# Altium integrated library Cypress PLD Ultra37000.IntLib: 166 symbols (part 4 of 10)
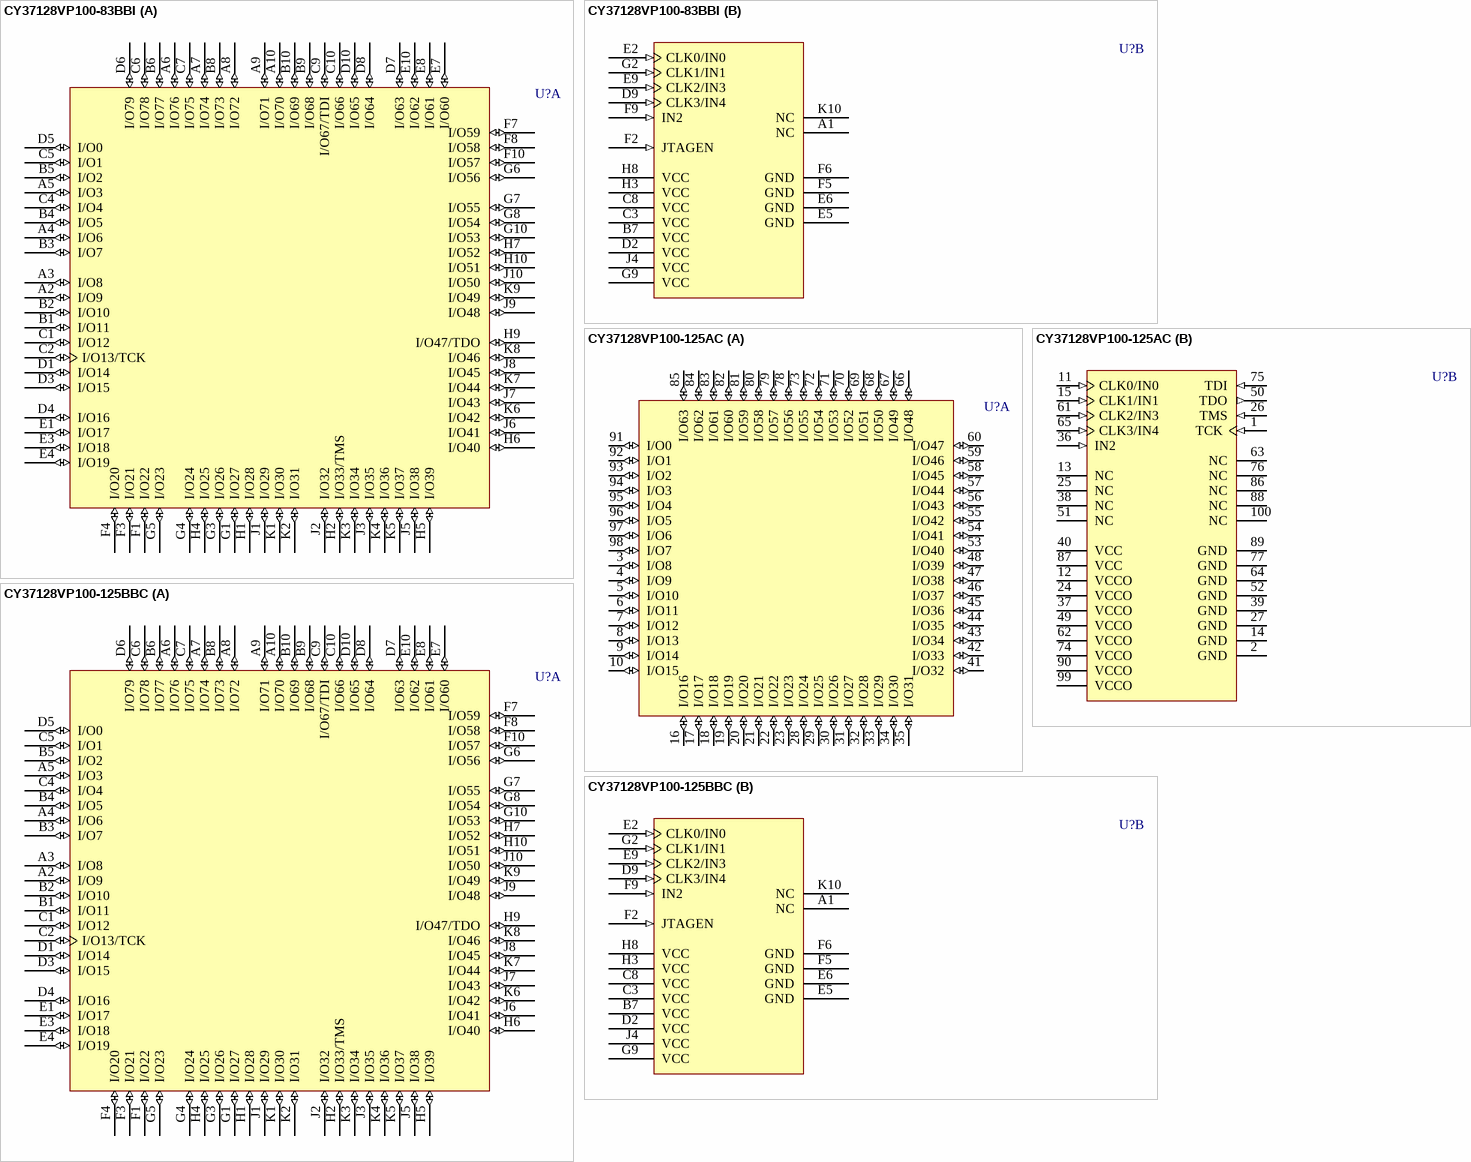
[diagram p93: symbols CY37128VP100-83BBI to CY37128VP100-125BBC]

## CY37128VP100-125AC
designator U?
Ultra37000 3.3V, ISR High-Performance CPLD
footprint A100_N (Thin QFP, 100-Leads, Body 14x14mm, Pitch 0.5mm, IPC Medium Density)
footprint A100_L (Thin QFP, 100-Leads, Body 14x14mm, Pitch 0.5mm, IPC High Density)
footprint A100_M (Thin QFP, 100-Leads, Body 14x14mm, Pitch 0.5mm, IPC Low Density)
3D model CY37128VP100-A100 (100-Pin Thin Quad Flat Pack 0.5 mm Pitch)
part A pins: 3 I/O8 (io), 4 I/O9 (io), 5 I/O10 (io), 6 I/O11 (io), 7 I/O12 (io), 8 I/O13 (io), 9 I/O14 (io), 10 I/O15 (io), 16 I/O16 (io), 17 I/O17 (io), 18 I/O18 (io), 19 I/O19 (io), 20 I/O20 (io), 21 I/O21 (io), 22 I/O22 (io), 23 I/O23 (io), 28 I/O24 (io), 29 I/O25 (io), 30 I/O26 (io), 31 I/O27 (io), 32 I/O28 (io), 33 I/O29 (io), 34 I/O30 (io), 35 I/O31 (io), 41 I/O32 (io), 42 I/O33 (io), 43 I/O34 (io), 44 I/O35 (io), 45 I/O36 (io), 46 I/O37 (io), 47 I/O38 (io), 48 I/O39 (io), 53 I/O40 (io), 54 I/O41 (io), 55 I/O42 (io), 56 I/O43 (io), 57 I/O44 (io), 58 I/O45 (io), 59 I/O46 (io), 60 I/O47 (io), 66 I/O48 (io), 67 I/O49 (io), 68 I/O50 (io), 69 I/O51 (io), 70 I/O52 (io), 71 I/O53 (io), 72 I/O54 (io), 73 I/O55 (io), 78 I/O56 (io), 79 I/O57 (io), 80 I/O58 (io), 81 I/O59 (io), 82 I/O60 (io), 83 I/O61 (io), 84 I/O62 (io), 85 I/O63 (io), 91 I/O0 (io), 92 I/O1 (io), 93 I/O2 (io), 94 I/O3 (io), 95 I/O4 (io), 96 I/O5 (io), 97 I/O6 (io), 98 I/O7 (io)
part B pins: 1 TCK (in), 2 GND (power), 11 CLK0/IN0 (in), 12 VCCO (power), 13 NC, 14 GND (power), 15 CLK1/IN1 (in), 24 VCCO (power), 25 NC, 26 TMS (in), 27 GND (power), 36 IN2 (in), 37 VCCO (power), 38 NC, 39 GND (power), 40 VCC (power), 49 VCCO (power), 50 TDO (out), 51 NC, 52 GND (power), 61 CLK2/IN3 (in), 62 VCCO (power), 63 NC, 64 GND (power), 65 CLK3/IN4 (in), 74 VCCO (power), 75 TDI (in), 76 NC, 77 GND (power), 86 NC, 87 VCC (power), 88 NC, 89 GND (power), 90 VCCO (power), 99 VCCO (power), 100 NC

## CY37128VP100-125BBC
designator U?
Ultra37000 3.3V, ISR High-Performance CPLD
footprint BB100 (BGA, 100-Leads, Body 11x11mm, Pitch 1mm)
3D model CY37128VP100-BB100 (100-Ball Thin Ball Grid Array 1 mm Pitch)
part A pins: A2 I/O9 (io), A3 I/O8 (io), A4 I/O6 (io), A5 I/O3 (io), A6 I/O76 (io), A7 I/O74 (io), A8 I/O72 (io), A9 I/O71 (io), A10 I/O70 (io), B1 I/O11 (io), B2 I/O10 (io), B3 I/O7 (io), B4 I/O5 (io), B5 I/O2 (io), B6 I/O77 (io), B8 I/O73 (io), B9 I/O68 (io), B10 I/O69 (io), C1 I/O12 (io), C2 I/O13/TCK (io), C4 I/O4 (io), C5 I/O1 (io), C6 I/O78 (io), C7 I/O75 (io), C9 I/O67/TDI (io), C10 I/O66 (io), D1 I/O14 (io), D3 I/O15 (io), D4 I/O16 (io), D5 I/O0 (io), D6 I/O79 (io), D7 I/O63 (io), D8 I/O64 (io), D10 I/O65 (io), E1 I/O17 (io), E3 I/O18 (io), E4 I/O19 (io), E7 I/O60 (io), E8 I/O61 (io), E10 I/O62 (io), F1 I/O22 (io), F3 I/O21 (io), F4 I/O20 (io), F7 I/O59 (io), F8 I/O58 (io), F10 I/O57 (io), G1 I/O27 (io), G3 I/O26 (io), G4 I/O24 (io), G5 I/O23 (io), G6 I/O56 (io), G7 I/O55 (io), G8 I/O54 (io), G10 I/O53 (io), H1 I/O28 (io), H2 I/O33/TMS (io), H4 I/O25 (io), H5 I/O39 (io), H6 I/O40 (io), H7 I/O52 (io), H9 I/O47/TDO (io), H10 I/O51 (io), J1 I/O29 (io), J2 I/O32 (io), J3 I/O35 (io), J5 I/O38 (io), J6 I/O41 (io), J7 I/O43 (io), J8 I/O45 (io), J9 I/O48 (io), J10 I/O50 (io), K1 I/O30 (io), K2 I/O31 (io), K3 I/O34 (io), K4 I/O36 (io), K5 I/O37 (io), K6 I/O42 (io), K7 I/O44 (io), K8 I/O46 (io), K9 I/O49 (io)
part B pins: A1 NC, B7 VCC (power), C3 VCC (power), C8 VCC (power), D2 VCC (power), D9 CLK3/IN4 (in), E2 CLK0/IN0 (in), E5 GND (power), E6 GND (power), E9 CLK2/IN3 (in), F2 JTAGEN (in), F5 GND (power), F6 GND (power), F9 IN2 (in), G2 CLK1/IN1 (in), G9 VCC (power), H3 VCC (power), H8 VCC (power), J4 VCC (power), K10 NC

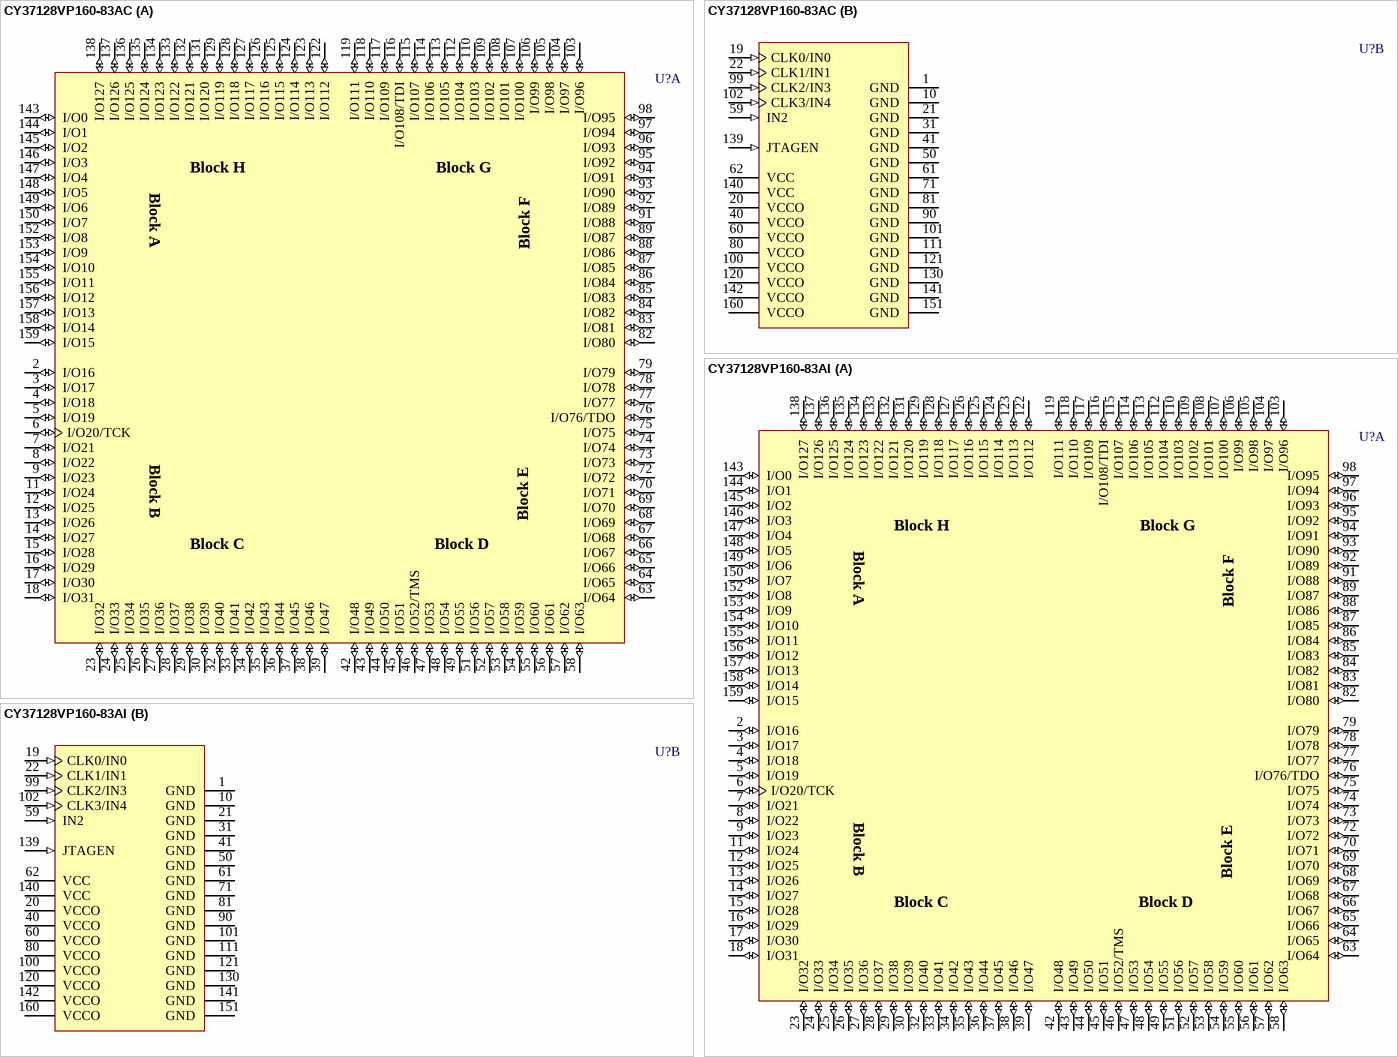
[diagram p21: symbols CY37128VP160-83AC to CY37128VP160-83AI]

## CY37128VP160-83AC
designator U?
Ultra37000 3.3V, ISR High-Performance CPLD
footprint A160_N (Thin QFP, 160-Leads, Body 24x24mm, Pitch 0.5mm, IPC Medium Density)
footprint A160_L (Thin QFP, 160-Leads, Body 24x24mm, Pitch 0.5mm, IPC High Density)
footprint A160_M (Thin QFP, 160-Leads, Body 24x24mm, Pitch 0.5mm, IPC Low Density)
3D model CY37128VP160-A160 (160-Pin Thin Quad Flat Pack 0.5 mm Pitch)
part A pins: 2 I/O16 (io), 3 I/O17 (io), 4 I/O18 (io), 5 I/O19 (io), 6 I/O20/TCK (io), 7 I/O21 (io), 8 I/O22 (io), 9 I/O23 (io), 11 I/O24 (io), 12 I/O25 (io), 13 I/O26 (io), 14 I/O27 (io), 15 I/O28 (io), 16 I/O29 (io), 17 I/O30 (io), 18 I/O31 (io), 23 I/O32 (io), 24 I/O33 (io), 25 I/O34 (io), 26 I/O35 (io), 27 I/O36 (io), 28 I/O37 (io), 29 I/O38 (io), 30 I/O39 (io), 32 I/O40 (io), 33 I/O41 (io), 34 I/O42 (io), 35 I/O43 (io), 36 I/O44 (io), 37 I/O45 (io), 38 I/O46 (io), 39 I/O47 (io), 42 I/O48 (io), 43 I/O49 (io), 44 I/O50 (io), 45 I/O51 (io), 46 I/O52/TMS (io), 47 I/O53 (io), 48 I/O54 (io), 49 I/O55 (io), 51 I/O56 (io), 52 I/O57 (io), 53 I/O58 (io), 54 I/O59 (io), 55 I/O60 (io), 56 I/O61 (io), 57 I/O62 (io), 58 I/O63 (io), 63 I/O64 (io), 64 I/O65 (io), 65 I/O66 (io), 66 I/O67 (io), 67 I/O68 (io), 68 I/O69 (io), 69 I/O70 (io), 70 I/O71 (io), 72 I/O72 (io), 73 I/O73 (io), 74 I/O74 (io), 75 I/O75 (io), 76 I/O76/TDO (io), 77 I/O77 (io), 78 I/O78 (io), 79 I/O79 (io), 82 I/O80 (io), 83 I/O81 (io), 84 I/O82 (io), 85 I/O83 (io), 86 I/O84 (io), 87 I/O85 (io), 88 I/O86 (io), 89 I/O87 (io), 91 I/O88 (io), 92 I/O89 (io), 93 I/O90 (io), 94 I/O91 (io), 95 I/O92 (io), 96 I/O93 (io), 97 I/O94 (io), 98 I/O95 (io), 103 I/O96 (io), 104 I/O97 (io), 105 I/O98 (io), 106 I/O99 (io), 107 I/O100 (io), 108 I/O101 (io), 109 I/O102 (io), 110 I/O103 (io), 112 I/O104 (io), 113 I/O105 (io), 114 I/O106 (io), 115 I/O107 (io), 116 I/O108/TDI (io), 117 I/O109 (io), 118 I/O110 (io), 119 I/O111 (io), 122 I/O112 (io), 123 I/O113 (io), 124 I/O114 (io), 125 I/O115 (io), 126 I/O116 (io), 127 I/O117 (io), 128 I/O118 (io), 129 I/O119 (io), 131 I/O120 (io), 132 I/O121 (io), 133 I/O122 (io), 134 I/O123 (io), 135 I/O124 (io), 136 I/O125 (io), 137 I/O126 (io), 138 I/O127 (io), 143 I/O0 (io), 144 I/O1 (io), 145 I/O2 (io), 146 I/O3 (io), 147 I/O4 (io), 148 I/O5 (io), 149 I/O6 (io), 150 I/O7 (io), 152 I/O8 (io), 153 I/O9 (io), 154 I/O10 (io), 155 I/O11 (io), 156 I/O12 (io), 157 I/O13 (io), 158 I/O14 (io), 159 I/O15 (io)
part B pins: 1 GND (power), 10 GND (power), 19 CLK0/IN0 (in), 20 VCCO (power), 21 GND (power), 22 CLK1/IN1 (in), 31 GND (power), 40 VCCO (power), 41 GND (power), 50 GND (power), 59 IN2 (in), 60 VCCO (power), 61 GND (power), 62 VCC (power), 71 GND (power), 80 VCCO (power), 81 GND (power), 90 GND (power), 99 CLK2/IN3 (in), 100 VCCO (power), 101 GND (power), 102 CLK3/IN4 (in), 111 GND (power), 120 VCCO (power), 121 GND (power), 130 GND (power), 139 JTAGEN (in), 140 VCC (power), 141 GND (power), 142 VCCO (power), 151 GND (power), 160 VCCO (power)

## CY37128VP160-83AI
designator U?
Ultra37000 3.3V, ISR High-Performance CPLD
footprint A160_N (Thin QFP, 160-Leads, Body 24x24mm, Pitch 0.5mm, IPC Medium Density)
footprint A160_L (Thin QFP, 160-Leads, Body 24x24mm, Pitch 0.5mm, IPC High Density)
footprint A160_M (Thin QFP, 160-Leads, Body 24x24mm, Pitch 0.5mm, IPC Low Density)
3D model CY37128VP160-A160 (160-Pin Thin Quad Flat Pack 0.5 mm Pitch)
part A pins: 2 I/O16 (io), 3 I/O17 (io), 4 I/O18 (io), 5 I/O19 (io), 6 I/O20/TCK (io), 7 I/O21 (io), 8 I/O22 (io), 9 I/O23 (io), 11 I/O24 (io), 12 I/O25 (io), 13 I/O26 (io), 14 I/O27 (io), 15 I/O28 (io), 16 I/O29 (io), 17 I/O30 (io), 18 I/O31 (io), 23 I/O32 (io), 24 I/O33 (io), 25 I/O34 (io), 26 I/O35 (io), 27 I/O36 (io), 28 I/O37 (io), 29 I/O38 (io), 30 I/O39 (io), 32 I/O40 (io), 33 I/O41 (io), 34 I/O42 (io), 35 I/O43 (io), 36 I/O44 (io), 37 I/O45 (io), 38 I/O46 (io), 39 I/O47 (io), 42 I/O48 (io), 43 I/O49 (io), 44 I/O50 (io), 45 I/O51 (io), 46 I/O52/TMS (io), 47 I/O53 (io), 48 I/O54 (io), 49 I/O55 (io), 51 I/O56 (io), 52 I/O57 (io), 53 I/O58 (io), 54 I/O59 (io), 55 I/O60 (io), 56 I/O61 (io), 57 I/O62 (io), 58 I/O63 (io), 63 I/O64 (io), 64 I/O65 (io), 65 I/O66 (io), 66 I/O67 (io), 67 I/O68 (io), 68 I/O69 (io), 69 I/O70 (io), 70 I/O71 (io), 72 I/O72 (io), 73 I/O73 (io), 74 I/O74 (io), 75 I/O75 (io), 76 I/O76/TDO (io), 77 I/O77 (io), 78 I/O78 (io), 79 I/O79 (io), 82 I/O80 (io), 83 I/O81 (io), 84 I/O82 (io), 85 I/O83 (io), 86 I/O84 (io), 87 I/O85 (io), 88 I/O86 (io), 89 I/O87 (io), 91 I/O88 (io), 92 I/O89 (io), 93 I/O90 (io), 94 I/O91 (io), 95 I/O92 (io), 96 I/O93 (io), 97 I/O94 (io), 98 I/O95 (io), 103 I/O96 (io), 104 I/O97 (io), 105 I/O98 (io), 106 I/O99 (io), 107 I/O100 (io), 108 I/O101 (io), 109 I/O102 (io), 110 I/O103 (io), 112 I/O104 (io), 113 I/O105 (io), 114 I/O106 (io), 115 I/O107 (io), 116 I/O108/TDI (io), 117 I/O109 (io), 118 I/O110 (io), 119 I/O111 (io), 122 I/O112 (io), 123 I/O113 (io), 124 I/O114 (io), 125 I/O115 (io), 126 I/O116 (io), 127 I/O117 (io), 128 I/O118 (io), 129 I/O119 (io), 131 I/O120 (io), 132 I/O121 (io), 133 I/O122 (io), 134 I/O123 (io), 135 I/O124 (io), 136 I/O125 (io), 137 I/O126 (io), 138 I/O127 (io), 143 I/O0 (io), 144 I/O1 (io), 145 I/O2 (io), 146 I/O3 (io), 147 I/O4 (io), 148 I/O5 (io), 149 I/O6 (io), 150 I/O7 (io), 152 I/O8 (io), 153 I/O9 (io), 154 I/O10 (io), 155 I/O11 (io), 156 I/O12 (io), 157 I/O13 (io), 158 I/O14 (io), 159 I/O15 (io)
part B pins: 1 GND (power), 10 GND (power), 19 CLK0/IN0 (in), 20 VCCO (power), 21 GND (power), 22 CLK1/IN1 (in), 31 GND (power), 40 VCCO (power), 41 GND (power), 50 GND (power), 59 IN2 (in), 60 VCCO (power), 61 GND (power), 62 VCC (power), 71 GND (power), 80 VCCO (power), 81 GND (power), 90 GND (power), 99 CLK2/IN3 (in), 100 VCCO (power), 101 GND (power), 102 CLK3/IN4 (in), 111 GND (power), 120 VCCO (power), 121 GND (power), 130 GND (power), 139 JTAGEN (in), 140 VCC (power), 141 GND (power), 142 VCCO (power), 151 GND (power), 160 VCCO (power)

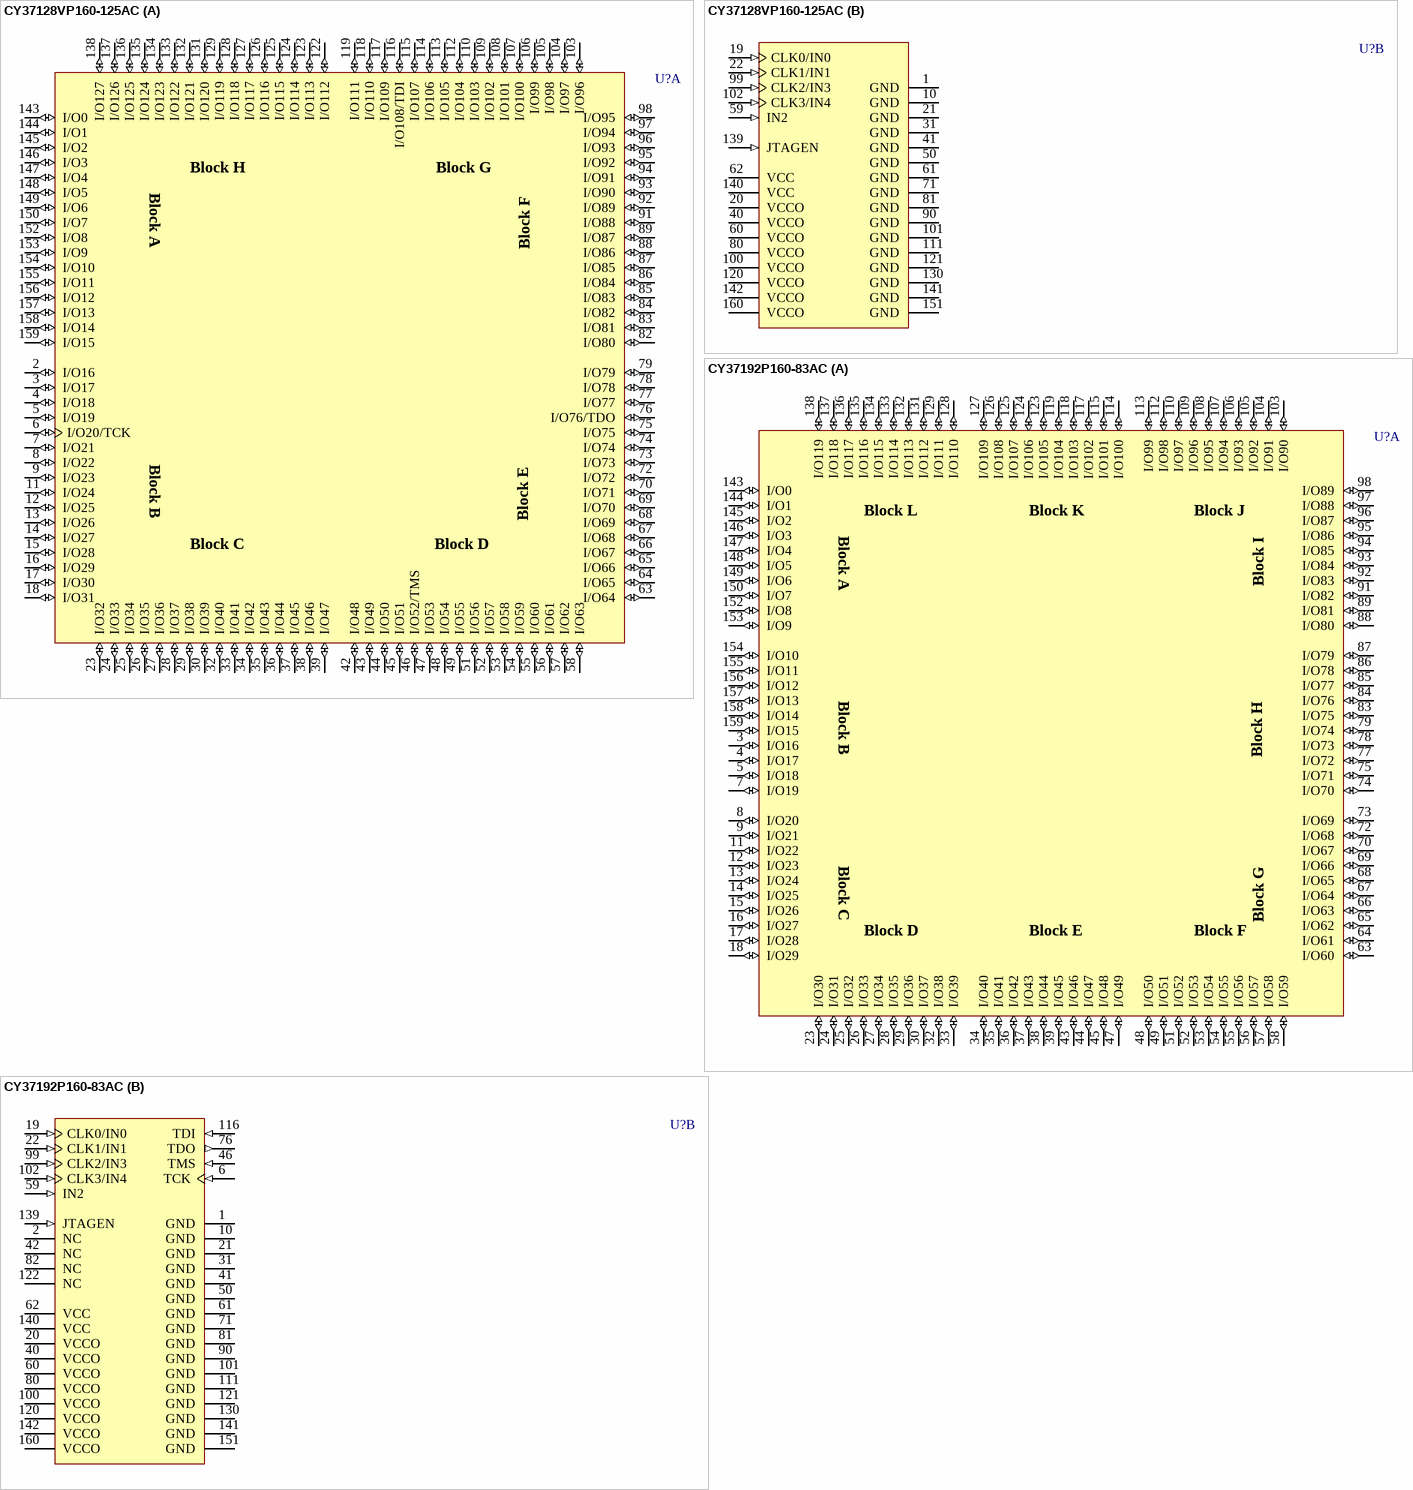
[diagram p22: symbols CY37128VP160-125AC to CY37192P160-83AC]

## CY37128VP160-125AC
designator U?
Ultra37000 3.3V, ISR High-Performance CPLD
footprint A160_N (Thin QFP, 160-Leads, Body 24x24mm, Pitch 0.5mm, IPC Medium Density)
footprint A160_L (Thin QFP, 160-Leads, Body 24x24mm, Pitch 0.5mm, IPC High Density)
footprint A160_M (Thin QFP, 160-Leads, Body 24x24mm, Pitch 0.5mm, IPC Low Density)
3D model CY37128VP160-A160 (160-Pin Thin Quad Flat Pack 0.5 mm Pitch)
part A pins: 2 I/O16 (io), 3 I/O17 (io), 4 I/O18 (io), 5 I/O19 (io), 6 I/O20/TCK (io), 7 I/O21 (io), 8 I/O22 (io), 9 I/O23 (io), 11 I/O24 (io), 12 I/O25 (io), 13 I/O26 (io), 14 I/O27 (io), 15 I/O28 (io), 16 I/O29 (io), 17 I/O30 (io), 18 I/O31 (io), 23 I/O32 (io), 24 I/O33 (io), 25 I/O34 (io), 26 I/O35 (io), 27 I/O36 (io), 28 I/O37 (io), 29 I/O38 (io), 30 I/O39 (io), 32 I/O40 (io), 33 I/O41 (io), 34 I/O42 (io), 35 I/O43 (io), 36 I/O44 (io), 37 I/O45 (io), 38 I/O46 (io), 39 I/O47 (io), 42 I/O48 (io), 43 I/O49 (io), 44 I/O50 (io), 45 I/O51 (io), 46 I/O52/TMS (io), 47 I/O53 (io), 48 I/O54 (io), 49 I/O55 (io), 51 I/O56 (io), 52 I/O57 (io), 53 I/O58 (io), 54 I/O59 (io), 55 I/O60 (io), 56 I/O61 (io), 57 I/O62 (io), 58 I/O63 (io), 63 I/O64 (io), 64 I/O65 (io), 65 I/O66 (io), 66 I/O67 (io), 67 I/O68 (io), 68 I/O69 (io), 69 I/O70 (io), 70 I/O71 (io), 72 I/O72 (io), 73 I/O73 (io), 74 I/O74 (io), 75 I/O75 (io), 76 I/O76/TDO (io), 77 I/O77 (io), 78 I/O78 (io), 79 I/O79 (io), 82 I/O80 (io), 83 I/O81 (io), 84 I/O82 (io), 85 I/O83 (io), 86 I/O84 (io), 87 I/O85 (io), 88 I/O86 (io), 89 I/O87 (io), 91 I/O88 (io), 92 I/O89 (io), 93 I/O90 (io), 94 I/O91 (io), 95 I/O92 (io), 96 I/O93 (io), 97 I/O94 (io), 98 I/O95 (io), 103 I/O96 (io), 104 I/O97 (io), 105 I/O98 (io), 106 I/O99 (io), 107 I/O100 (io), 108 I/O101 (io), 109 I/O102 (io), 110 I/O103 (io), 112 I/O104 (io), 113 I/O105 (io), 114 I/O106 (io), 115 I/O107 (io), 116 I/O108/TDI (io), 117 I/O109 (io), 118 I/O110 (io), 119 I/O111 (io), 122 I/O112 (io), 123 I/O113 (io), 124 I/O114 (io), 125 I/O115 (io), 126 I/O116 (io), 127 I/O117 (io), 128 I/O118 (io), 129 I/O119 (io), 131 I/O120 (io), 132 I/O121 (io), 133 I/O122 (io), 134 I/O123 (io), 135 I/O124 (io), 136 I/O125 (io), 137 I/O126 (io), 138 I/O127 (io), 143 I/O0 (io), 144 I/O1 (io), 145 I/O2 (io), 146 I/O3 (io), 147 I/O4 (io), 148 I/O5 (io), 149 I/O6 (io), 150 I/O7 (io), 152 I/O8 (io), 153 I/O9 (io), 154 I/O10 (io), 155 I/O11 (io), 156 I/O12 (io), 157 I/O13 (io), 158 I/O14 (io), 159 I/O15 (io)
part B pins: 1 GND (power), 10 GND (power), 19 CLK0/IN0 (in), 20 VCCO (power), 21 GND (power), 22 CLK1/IN1 (in), 31 GND (power), 40 VCCO (power), 41 GND (power), 50 GND (power), 59 IN2 (in), 60 VCCO (power), 61 GND (power), 62 VCC (power), 71 GND (power), 80 VCCO (power), 81 GND (power), 90 GND (power), 99 CLK2/IN3 (in), 100 VCCO (power), 101 GND (power), 102 CLK3/IN4 (in), 111 GND (power), 120 VCCO (power), 121 GND (power), 130 GND (power), 139 JTAGEN (in), 140 VCC (power), 141 GND (power), 142 VCCO (power), 151 GND (power), 160 VCCO (power)

## CY37192P160-83AC
designator U?
Ultra37000 5V, ISR High-Performance CPLD
footprint A160_N (Thin QFP, 160-Leads, Body 24x24mm, Pitch 0.5mm, IPC Medium Density)
footprint A160_L (Thin QFP, 160-Leads, Body 24x24mm, Pitch 0.5mm, IPC High Density)
footprint A160_M (Thin QFP, 160-Leads, Body 24x24mm, Pitch 0.5mm, IPC Low Density)
3D model CY37192P160-A160 (160-Pin Thin Quad Flat Pack 0.5 mm Pitch)
part A pins: 3 I/O16 (io), 4 I/O17 (io), 5 I/O18 (io), 7 I/O19 (io), 8 I/O20 (io), 9 I/O21 (io), 11 I/O22 (io), 12 I/O23 (io), 13 I/O24 (io), 14 I/O25 (io), 15 I/O26 (io), 16 I/O27 (io), 17 I/O28 (io), 18 I/O29 (io), 23 I/O30 (io), 24 I/O31 (io), 25 I/O32 (io), 26 I/O33 (io), 27 I/O34 (io), 28 I/O35 (io), 29 I/O36 (io), 30 I/O37 (io), 32 I/O38 (io), 33 I/O39 (io), 34 I/O40 (io), 35 I/O41 (io), 36 I/O42 (io), 37 I/O43 (io), 38 I/O44 (io), 39 I/O45 (io), 43 I/O46 (io), 44 I/O47 (io), 45 I/O48 (io), 47 I/O49 (io), 48 I/O50 (io), 49 I/O51 (io), 51 I/O52 (io), 52 I/O53 (io), 53 I/O54 (io), 54 I/O55 (io), 55 I/O56 (io), 56 I/O57 (io), 57 I/O58 (io), 58 I/O59 (io), 63 I/O60 (io), 64 I/O61 (io), 65 I/O62 (io), 66 I/O63 (io), 67 I/O64 (io), 68 I/O65 (io), 69 I/O66 (io), 70 I/O67 (io), 72 I/O68 (io), 73 I/O69 (io), 74 I/O70 (io), 75 I/O71 (io), 77 I/O72 (io), 78 I/O73 (io), 79 I/O74 (io), 83 I/O75 (io), 84 I/O76 (io), 85 I/O77 (io), 86 I/O78 (io), 87 I/O79 (io), 88 I/O80 (io), 89 I/O81 (io), 91 I/O82 (io), 92 I/O83 (io), 93 I/O84 (io), 94 I/O85 (io), 95 I/O86 (io), 96 I/O87 (io), 97 I/O88 (io), 98 I/O89 (io), 103 I/O90 (io), 104 I/O91 (io), 105 I/O92 (io), 106 I/O93 (io), 107 I/O94 (io), 108 I/O95 (io), 109 I/O96 (io), 110 I/O97 (io), 112 I/O98 (io), 113 I/O99 (io), 114 I/O100 (io), 115 I/O101 (io), 117 I/O102 (io), 118 I/O103 (io), 119 I/O104 (io), 123 I/O105 (io), 124 I/O106 (io), 125 I/O107 (io), 126 I/O108 (io), 127 I/O109 (io), 128 I/O110 (io), 129 I/O111 (io), 131 I/O112 (io), 132 I/O113 (io), 133 I/O114 (io), 134 I/O115 (io), 135 I/O116 (io), 136 I/O117 (io), 137 I/O118 (io), 138 I/O119 (io), 143 I/O0 (io), 144 I/O1 (io), 145 I/O2 (io), 146 I/O3 (io), 147 I/O4 (io), 148 I/O5 (io), 149 I/O6 (io), 150 I/O7 (io), 152 I/O8 (io), 153 I/O9 (io), 154 I/O10 (io), 155 I/O11 (io), 156 I/O12 (io), 157 I/O13 (io), 158 I/O14 (io), 159 I/O15 (io)
part B pins: 1 GND (power), 2 NC, 6 TCK (in), 10 GND (power), 19 CLK0/IN0 (in), 20 VCCO (power), 21 GND (power), 22 CLK1/IN1 (in), 31 GND (power), 40 VCCO (power), 41 GND (power), 42 NC, 46 TMS (in), 50 GND (power), 59 IN2 (in), 60 VCCO (power), 61 GND (power), 62 VCC (power), 71 GND (power), 76 TDO (out), 80 VCCO (power), 81 GND (power), 82 NC, 90 GND (power), 99 CLK2/IN3 (in), 100 VCCO (power), 101 GND (power), 102 CLK3/IN4 (in), 111 GND (power), 116 TDI (in), 120 VCCO (power), 121 GND (power), 122 NC, 130 GND (power), 139 JTAGEN (in), 140 VCC (power), 141 GND (power), 142 VCCO (power), 151 GND (power), 160 VCCO (power)

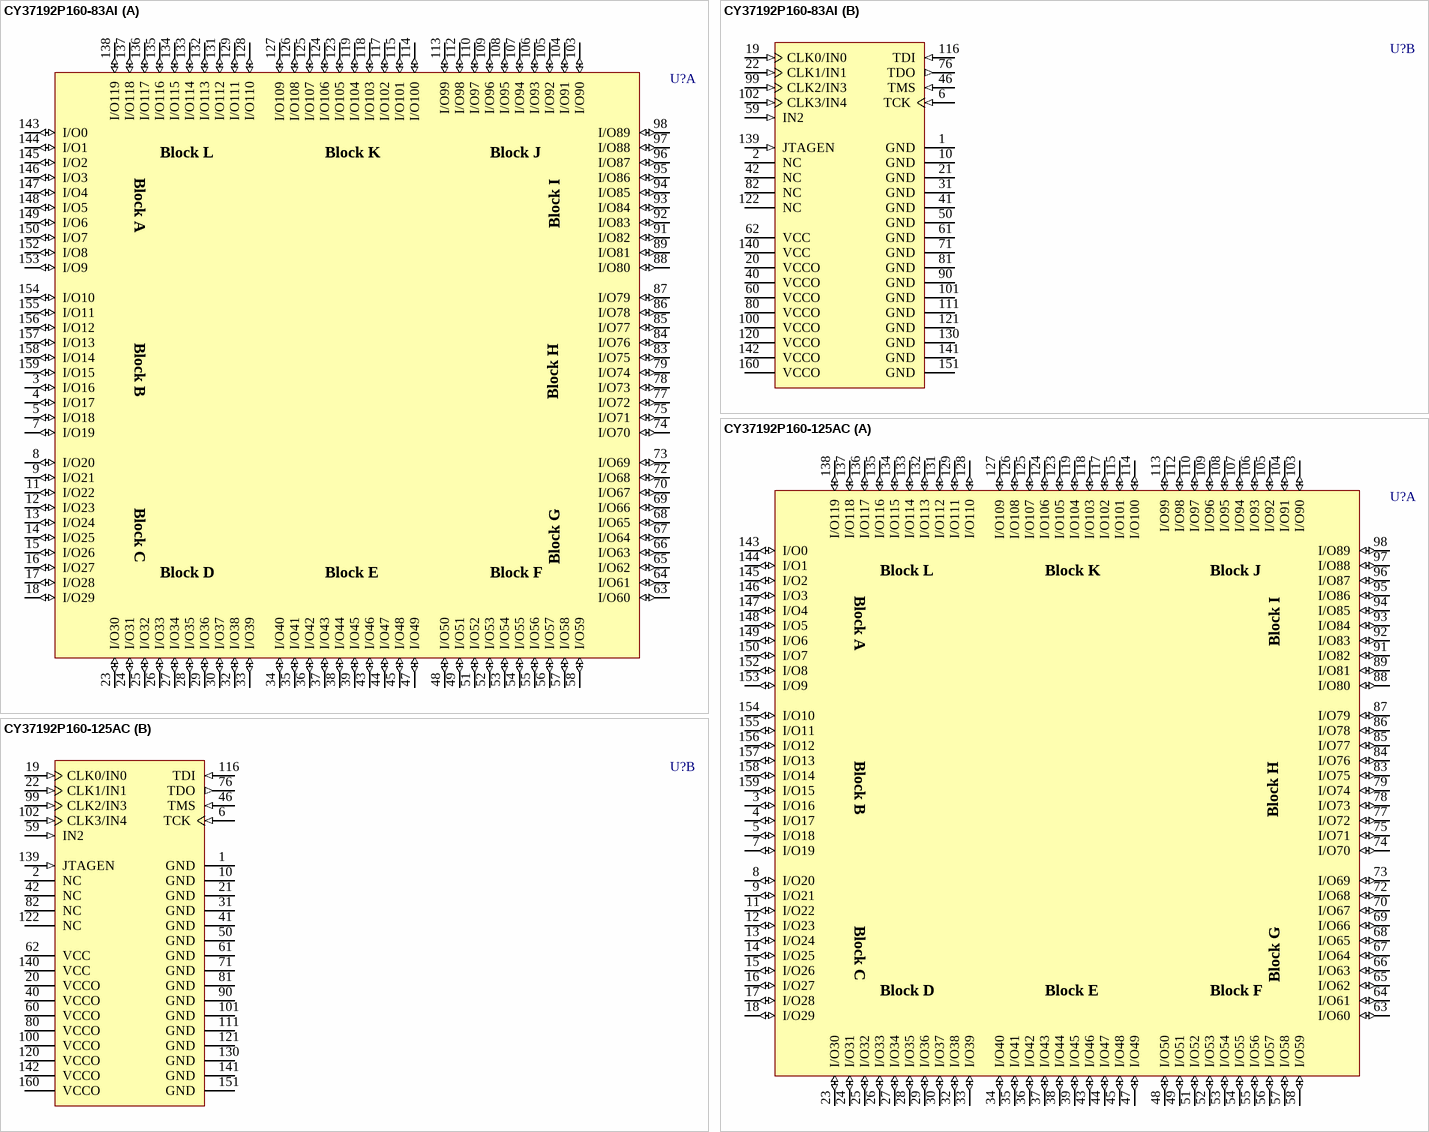
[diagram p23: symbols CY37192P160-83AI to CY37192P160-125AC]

## CY37192P160-83AI
designator U?
Ultra37000 5V, ISR High-Performance CPLD
footprint A160_N (Thin QFP, 160-Leads, Body 24x24mm, Pitch 0.5mm, IPC Medium Density)
footprint A160_L (Thin QFP, 160-Leads, Body 24x24mm, Pitch 0.5mm, IPC High Density)
footprint A160_M (Thin QFP, 160-Leads, Body 24x24mm, Pitch 0.5mm, IPC Low Density)
3D model CY37192P160-A160 (160-Pin Thin Quad Flat Pack 0.5 mm Pitch)
part A pins: 3 I/O16 (io), 4 I/O17 (io), 5 I/O18 (io), 7 I/O19 (io), 8 I/O20 (io), 9 I/O21 (io), 11 I/O22 (io), 12 I/O23 (io), 13 I/O24 (io), 14 I/O25 (io), 15 I/O26 (io), 16 I/O27 (io), 17 I/O28 (io), 18 I/O29 (io), 23 I/O30 (io), 24 I/O31 (io), 25 I/O32 (io), 26 I/O33 (io), 27 I/O34 (io), 28 I/O35 (io), 29 I/O36 (io), 30 I/O37 (io), 32 I/O38 (io), 33 I/O39 (io), 34 I/O40 (io), 35 I/O41 (io), 36 I/O42 (io), 37 I/O43 (io), 38 I/O44 (io), 39 I/O45 (io), 43 I/O46 (io), 44 I/O47 (io), 45 I/O48 (io), 47 I/O49 (io), 48 I/O50 (io), 49 I/O51 (io), 51 I/O52 (io), 52 I/O53 (io), 53 I/O54 (io), 54 I/O55 (io), 55 I/O56 (io), 56 I/O57 (io), 57 I/O58 (io), 58 I/O59 (io), 63 I/O60 (io), 64 I/O61 (io), 65 I/O62 (io), 66 I/O63 (io), 67 I/O64 (io), 68 I/O65 (io), 69 I/O66 (io), 70 I/O67 (io), 72 I/O68 (io), 73 I/O69 (io), 74 I/O70 (io), 75 I/O71 (io), 77 I/O72 (io), 78 I/O73 (io), 79 I/O74 (io), 83 I/O75 (io), 84 I/O76 (io), 85 I/O77 (io), 86 I/O78 (io), 87 I/O79 (io), 88 I/O80 (io), 89 I/O81 (io), 91 I/O82 (io), 92 I/O83 (io), 93 I/O84 (io), 94 I/O85 (io), 95 I/O86 (io), 96 I/O87 (io), 97 I/O88 (io), 98 I/O89 (io), 103 I/O90 (io), 104 I/O91 (io), 105 I/O92 (io), 106 I/O93 (io), 107 I/O94 (io), 108 I/O95 (io), 109 I/O96 (io), 110 I/O97 (io), 112 I/O98 (io), 113 I/O99 (io), 114 I/O100 (io), 115 I/O101 (io), 117 I/O102 (io), 118 I/O103 (io), 119 I/O104 (io), 123 I/O105 (io), 124 I/O106 (io), 125 I/O107 (io), 126 I/O108 (io), 127 I/O109 (io), 128 I/O110 (io), 129 I/O111 (io), 131 I/O112 (io), 132 I/O113 (io), 133 I/O114 (io), 134 I/O115 (io), 135 I/O116 (io), 136 I/O117 (io), 137 I/O118 (io), 138 I/O119 (io), 143 I/O0 (io), 144 I/O1 (io), 145 I/O2 (io), 146 I/O3 (io), 147 I/O4 (io), 148 I/O5 (io), 149 I/O6 (io), 150 I/O7 (io), 152 I/O8 (io), 153 I/O9 (io), 154 I/O10 (io), 155 I/O11 (io), 156 I/O12 (io), 157 I/O13 (io), 158 I/O14 (io), 159 I/O15 (io)
part B pins: 1 GND (power), 2 NC, 6 TCK (in), 10 GND (power), 19 CLK0/IN0 (in), 20 VCCO (power), 21 GND (power), 22 CLK1/IN1 (in), 31 GND (power), 40 VCCO (power), 41 GND (power), 42 NC, 46 TMS (in), 50 GND (power), 59 IN2 (in), 60 VCCO (power), 61 GND (power), 62 VCC (power), 71 GND (power), 76 TDO (out), 80 VCCO (power), 81 GND (power), 82 NC, 90 GND (power), 99 CLK2/IN3 (in), 100 VCCO (power), 101 GND (power), 102 CLK3/IN4 (in), 111 GND (power), 116 TDI (in), 120 VCCO (power), 121 GND (power), 122 NC, 130 GND (power), 139 JTAGEN (in), 140 VCC (power), 141 GND (power), 142 VCCO (power), 151 GND (power), 160 VCCO (power)

## CY37192P160-125AC
designator U?
Ultra37000 5V, ISR High-Performance CPLD
footprint A160_N (Thin QFP, 160-Leads, Body 24x24mm, Pitch 0.5mm, IPC Medium Density)
footprint A160_L (Thin QFP, 160-Leads, Body 24x24mm, Pitch 0.5mm, IPC High Density)
footprint A160_M (Thin QFP, 160-Leads, Body 24x24mm, Pitch 0.5mm, IPC Low Density)
3D model CY37192P160-A160 (160-Pin Thin Quad Flat Pack 0.5 mm Pitch)
part A pins: 3 I/O16 (io), 4 I/O17 (io), 5 I/O18 (io), 7 I/O19 (io), 8 I/O20 (io), 9 I/O21 (io), 11 I/O22 (io), 12 I/O23 (io), 13 I/O24 (io), 14 I/O25 (io), 15 I/O26 (io), 16 I/O27 (io), 17 I/O28 (io), 18 I/O29 (io), 23 I/O30 (io), 24 I/O31 (io), 25 I/O32 (io), 26 I/O33 (io), 27 I/O34 (io), 28 I/O35 (io), 29 I/O36 (io), 30 I/O37 (io), 32 I/O38 (io), 33 I/O39 (io), 34 I/O40 (io), 35 I/O41 (io), 36 I/O42 (io), 37 I/O43 (io), 38 I/O44 (io), 39 I/O45 (io), 43 I/O46 (io), 44 I/O47 (io), 45 I/O48 (io), 47 I/O49 (io), 48 I/O50 (io), 49 I/O51 (io), 51 I/O52 (io), 52 I/O53 (io), 53 I/O54 (io), 54 I/O55 (io), 55 I/O56 (io), 56 I/O57 (io), 57 I/O58 (io), 58 I/O59 (io), 63 I/O60 (io), 64 I/O61 (io), 65 I/O62 (io), 66 I/O63 (io), 67 I/O64 (io), 68 I/O65 (io), 69 I/O66 (io), 70 I/O67 (io), 72 I/O68 (io), 73 I/O69 (io), 74 I/O70 (io), 75 I/O71 (io), 77 I/O72 (io), 78 I/O73 (io), 79 I/O74 (io), 83 I/O75 (io), 84 I/O76 (io), 85 I/O77 (io), 86 I/O78 (io), 87 I/O79 (io), 88 I/O80 (io), 89 I/O81 (io), 91 I/O82 (io), 92 I/O83 (io), 93 I/O84 (io), 94 I/O85 (io), 95 I/O86 (io), 96 I/O87 (io), 97 I/O88 (io), 98 I/O89 (io), 103 I/O90 (io), 104 I/O91 (io), 105 I/O92 (io), 106 I/O93 (io), 107 I/O94 (io), 108 I/O95 (io), 109 I/O96 (io), 110 I/O97 (io), 112 I/O98 (io), 113 I/O99 (io), 114 I/O100 (io), 115 I/O101 (io), 117 I/O102 (io), 118 I/O103 (io), 119 I/O104 (io), 123 I/O105 (io), 124 I/O106 (io), 125 I/O107 (io), 126 I/O108 (io), 127 I/O109 (io), 128 I/O110 (io), 129 I/O111 (io), 131 I/O112 (io), 132 I/O113 (io), 133 I/O114 (io), 134 I/O115 (io), 135 I/O116 (io), 136 I/O117 (io), 137 I/O118 (io), 138 I/O119 (io), 143 I/O0 (io), 144 I/O1 (io), 145 I/O2 (io), 146 I/O3 (io), 147 I/O4 (io), 148 I/O5 (io), 149 I/O6 (io), 150 I/O7 (io), 152 I/O8 (io), 153 I/O9 (io), 154 I/O10 (io), 155 I/O11 (io), 156 I/O12 (io), 157 I/O13 (io), 158 I/O14 (io), 159 I/O15 (io)
part B pins: 1 GND (power), 2 NC, 6 TCK (in), 10 GND (power), 19 CLK0/IN0 (in), 20 VCCO (power), 21 GND (power), 22 CLK1/IN1 (in), 31 GND (power), 40 VCCO (power), 41 GND (power), 42 NC, 46 TMS (in), 50 GND (power), 59 IN2 (in), 60 VCCO (power), 61 GND (power), 62 VCC (power), 71 GND (power), 76 TDO (out), 80 VCCO (power), 81 GND (power), 82 NC, 90 GND (power), 99 CLK2/IN3 (in), 100 VCCO (power), 101 GND (power), 102 CLK3/IN4 (in), 111 GND (power), 116 TDI (in), 120 VCCO (power), 121 GND (power), 122 NC, 130 GND (power), 139 JTAGEN (in), 140 VCC (power), 141 GND (power), 142 VCCO (power), 151 GND (power), 160 VCCO (power)

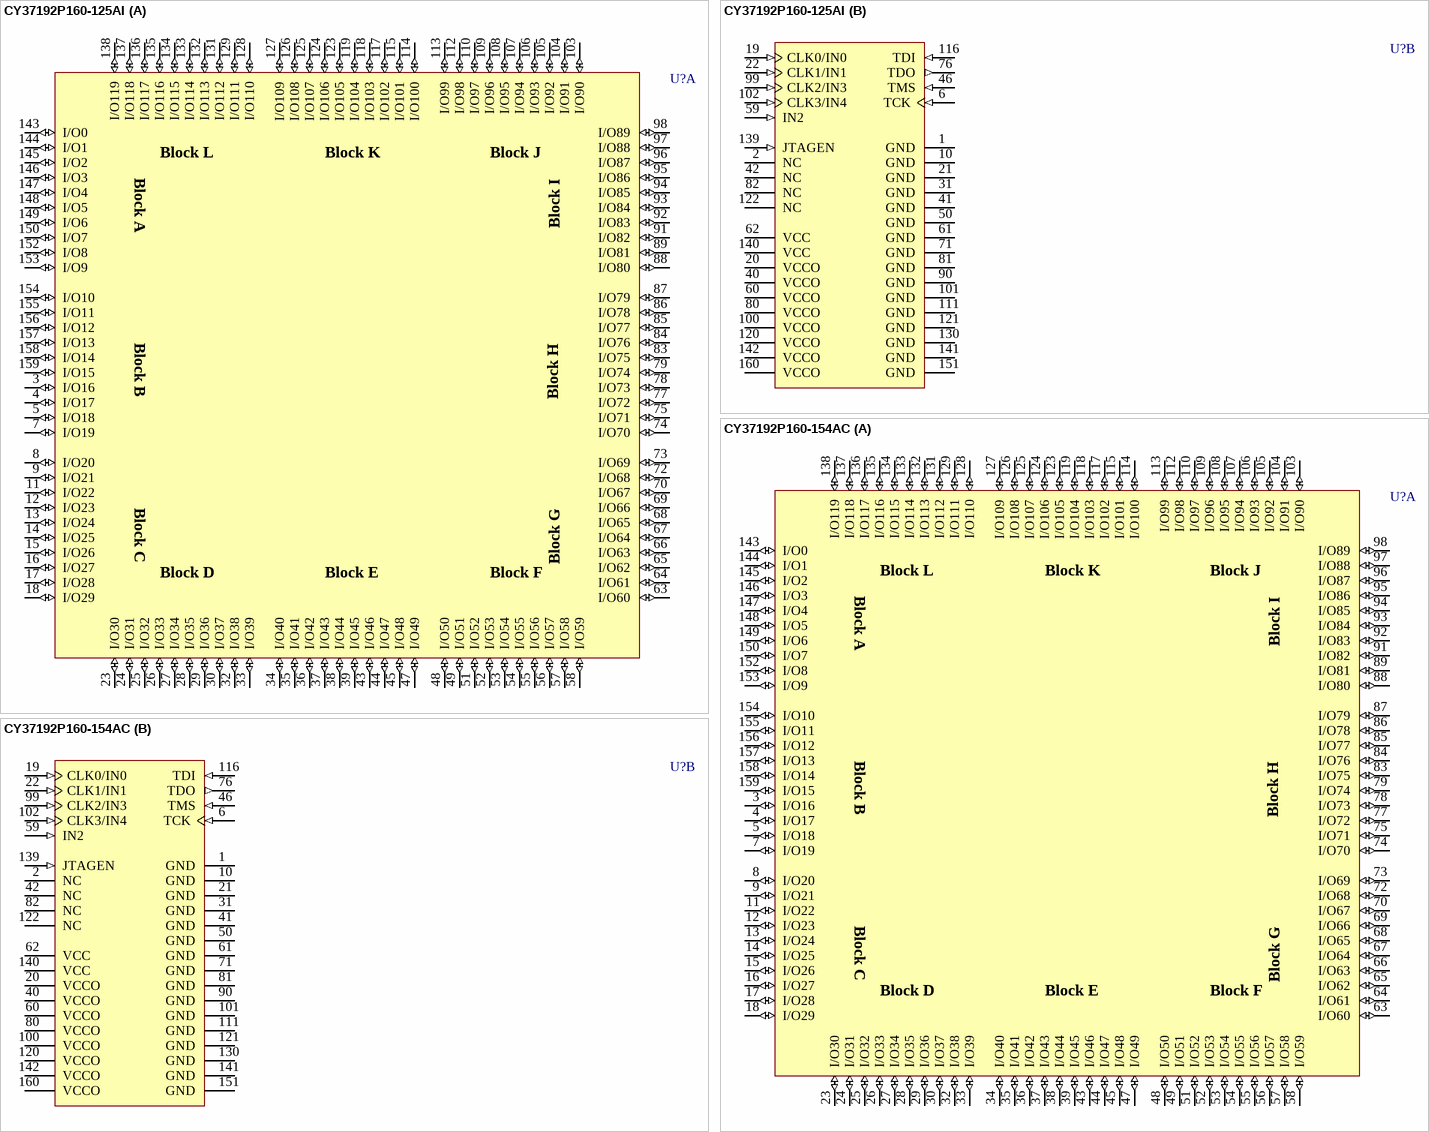
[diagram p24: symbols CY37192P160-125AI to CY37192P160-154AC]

## CY37192P160-125AI
designator U?
Ultra37000 5V, ISR High-Performance CPLD
footprint A160_N (Thin QFP, 160-Leads, Body 24x24mm, Pitch 0.5mm, IPC Medium Density)
footprint A160_L (Thin QFP, 160-Leads, Body 24x24mm, Pitch 0.5mm, IPC High Density)
footprint A160_M (Thin QFP, 160-Leads, Body 24x24mm, Pitch 0.5mm, IPC Low Density)
3D model CY37192P160-A160 (160-Pin Thin Quad Flat Pack 0.5 mm Pitch)
part A pins: 3 I/O16 (io), 4 I/O17 (io), 5 I/O18 (io), 7 I/O19 (io), 8 I/O20 (io), 9 I/O21 (io), 11 I/O22 (io), 12 I/O23 (io), 13 I/O24 (io), 14 I/O25 (io), 15 I/O26 (io), 16 I/O27 (io), 17 I/O28 (io), 18 I/O29 (io), 23 I/O30 (io), 24 I/O31 (io), 25 I/O32 (io), 26 I/O33 (io), 27 I/O34 (io), 28 I/O35 (io), 29 I/O36 (io), 30 I/O37 (io), 32 I/O38 (io), 33 I/O39 (io), 34 I/O40 (io), 35 I/O41 (io), 36 I/O42 (io), 37 I/O43 (io), 38 I/O44 (io), 39 I/O45 (io), 43 I/O46 (io), 44 I/O47 (io), 45 I/O48 (io), 47 I/O49 (io), 48 I/O50 (io), 49 I/O51 (io), 51 I/O52 (io), 52 I/O53 (io), 53 I/O54 (io), 54 I/O55 (io), 55 I/O56 (io), 56 I/O57 (io), 57 I/O58 (io), 58 I/O59 (io), 63 I/O60 (io), 64 I/O61 (io), 65 I/O62 (io), 66 I/O63 (io), 67 I/O64 (io), 68 I/O65 (io), 69 I/O66 (io), 70 I/O67 (io), 72 I/O68 (io), 73 I/O69 (io), 74 I/O70 (io), 75 I/O71 (io), 77 I/O72 (io), 78 I/O73 (io), 79 I/O74 (io), 83 I/O75 (io), 84 I/O76 (io), 85 I/O77 (io), 86 I/O78 (io), 87 I/O79 (io), 88 I/O80 (io), 89 I/O81 (io), 91 I/O82 (io), 92 I/O83 (io), 93 I/O84 (io), 94 I/O85 (io), 95 I/O86 (io), 96 I/O87 (io), 97 I/O88 (io), 98 I/O89 (io), 103 I/O90 (io), 104 I/O91 (io), 105 I/O92 (io), 106 I/O93 (io), 107 I/O94 (io), 108 I/O95 (io), 109 I/O96 (io), 110 I/O97 (io), 112 I/O98 (io), 113 I/O99 (io), 114 I/O100 (io), 115 I/O101 (io), 117 I/O102 (io), 118 I/O103 (io), 119 I/O104 (io), 123 I/O105 (io), 124 I/O106 (io), 125 I/O107 (io), 126 I/O108 (io), 127 I/O109 (io), 128 I/O110 (io), 129 I/O111 (io), 131 I/O112 (io), 132 I/O113 (io), 133 I/O114 (io), 134 I/O115 (io), 135 I/O116 (io), 136 I/O117 (io), 137 I/O118 (io), 138 I/O119 (io), 143 I/O0 (io), 144 I/O1 (io), 145 I/O2 (io), 146 I/O3 (io), 147 I/O4 (io), 148 I/O5 (io), 149 I/O6 (io), 150 I/O7 (io), 152 I/O8 (io), 153 I/O9 (io), 154 I/O10 (io), 155 I/O11 (io), 156 I/O12 (io), 157 I/O13 (io), 158 I/O14 (io), 159 I/O15 (io)
part B pins: 1 GND (power), 2 NC, 6 TCK (in), 10 GND (power), 19 CLK0/IN0 (in), 20 VCCO (power), 21 GND (power), 22 CLK1/IN1 (in), 31 GND (power), 40 VCCO (power), 41 GND (power), 42 NC, 46 TMS (in), 50 GND (power), 59 IN2 (in), 60 VCCO (power), 61 GND (power), 62 VCC (power), 71 GND (power), 76 TDO (out), 80 VCCO (power), 81 GND (power), 82 NC, 90 GND (power), 99 CLK2/IN3 (in), 100 VCCO (power), 101 GND (power), 102 CLK3/IN4 (in), 111 GND (power), 116 TDI (in), 120 VCCO (power), 121 GND (power), 122 NC, 130 GND (power), 139 JTAGEN (in), 140 VCC (power), 141 GND (power), 142 VCCO (power), 151 GND (power), 160 VCCO (power)

## CY37192P160-154AC
designator U?
Ultra37000 5V, ISR High-Performance CPLD
footprint A160_N (Thin QFP, 160-Leads, Body 24x24mm, Pitch 0.5mm, IPC Medium Density)
footprint A160_L (Thin QFP, 160-Leads, Body 24x24mm, Pitch 0.5mm, IPC High Density)
footprint A160_M (Thin QFP, 160-Leads, Body 24x24mm, Pitch 0.5mm, IPC Low Density)
3D model CY37192P160-A160 (160-Pin Thin Quad Flat Pack 0.5 mm Pitch)
part A pins: 3 I/O16 (io), 4 I/O17 (io), 5 I/O18 (io), 7 I/O19 (io), 8 I/O20 (io), 9 I/O21 (io), 11 I/O22 (io), 12 I/O23 (io), 13 I/O24 (io), 14 I/O25 (io), 15 I/O26 (io), 16 I/O27 (io), 17 I/O28 (io), 18 I/O29 (io), 23 I/O30 (io), 24 I/O31 (io), 25 I/O32 (io), 26 I/O33 (io), 27 I/O34 (io), 28 I/O35 (io), 29 I/O36 (io), 30 I/O37 (io), 32 I/O38 (io), 33 I/O39 (io), 34 I/O40 (io), 35 I/O41 (io), 36 I/O42 (io), 37 I/O43 (io), 38 I/O44 (io), 39 I/O45 (io), 43 I/O46 (io), 44 I/O47 (io), 45 I/O48 (io), 47 I/O49 (io), 48 I/O50 (io), 49 I/O51 (io), 51 I/O52 (io), 52 I/O53 (io), 53 I/O54 (io), 54 I/O55 (io), 55 I/O56 (io), 56 I/O57 (io), 57 I/O58 (io), 58 I/O59 (io), 63 I/O60 (io), 64 I/O61 (io), 65 I/O62 (io), 66 I/O63 (io), 67 I/O64 (io), 68 I/O65 (io), 69 I/O66 (io), 70 I/O67 (io), 72 I/O68 (io), 73 I/O69 (io), 74 I/O70 (io), 75 I/O71 (io), 77 I/O72 (io), 78 I/O73 (io), 79 I/O74 (io), 83 I/O75 (io), 84 I/O76 (io), 85 I/O77 (io), 86 I/O78 (io), 87 I/O79 (io), 88 I/O80 (io), 89 I/O81 (io), 91 I/O82 (io), 92 I/O83 (io), 93 I/O84 (io), 94 I/O85 (io), 95 I/O86 (io), 96 I/O87 (io), 97 I/O88 (io), 98 I/O89 (io), 103 I/O90 (io), 104 I/O91 (io), 105 I/O92 (io), 106 I/O93 (io), 107 I/O94 (io), 108 I/O95 (io), 109 I/O96 (io), 110 I/O97 (io), 112 I/O98 (io), 113 I/O99 (io), 114 I/O100 (io), 115 I/O101 (io), 117 I/O102 (io), 118 I/O103 (io), 119 I/O104 (io), 123 I/O105 (io), 124 I/O106 (io), 125 I/O107 (io), 126 I/O108 (io), 127 I/O109 (io), 128 I/O110 (io), 129 I/O111 (io), 131 I/O112 (io), 132 I/O113 (io), 133 I/O114 (io), 134 I/O115 (io), 135 I/O116 (io), 136 I/O117 (io), 137 I/O118 (io), 138 I/O119 (io), 143 I/O0 (io), 144 I/O1 (io), 145 I/O2 (io), 146 I/O3 (io), 147 I/O4 (io), 148 I/O5 (io), 149 I/O6 (io), 150 I/O7 (io), 152 I/O8 (io), 153 I/O9 (io), 154 I/O10 (io), 155 I/O11 (io), 156 I/O12 (io), 157 I/O13 (io), 158 I/O14 (io), 159 I/O15 (io)
part B pins: 1 GND (power), 2 NC, 6 TCK (in), 10 GND (power), 19 CLK0/IN0 (in), 20 VCCO (power), 21 GND (power), 22 CLK1/IN1 (in), 31 GND (power), 40 VCCO (power), 41 GND (power), 42 NC, 46 TMS (in), 50 GND (power), 59 IN2 (in), 60 VCCO (power), 61 GND (power), 62 VCC (power), 71 GND (power), 76 TDO (out), 80 VCCO (power), 81 GND (power), 82 NC, 90 GND (power), 99 CLK2/IN3 (in), 100 VCCO (power), 101 GND (power), 102 CLK3/IN4 (in), 111 GND (power), 116 TDI (in), 120 VCCO (power), 121 GND (power), 122 NC, 130 GND (power), 139 JTAGEN (in), 140 VCC (power), 141 GND (power), 142 VCCO (power), 151 GND (power), 160 VCCO (power)

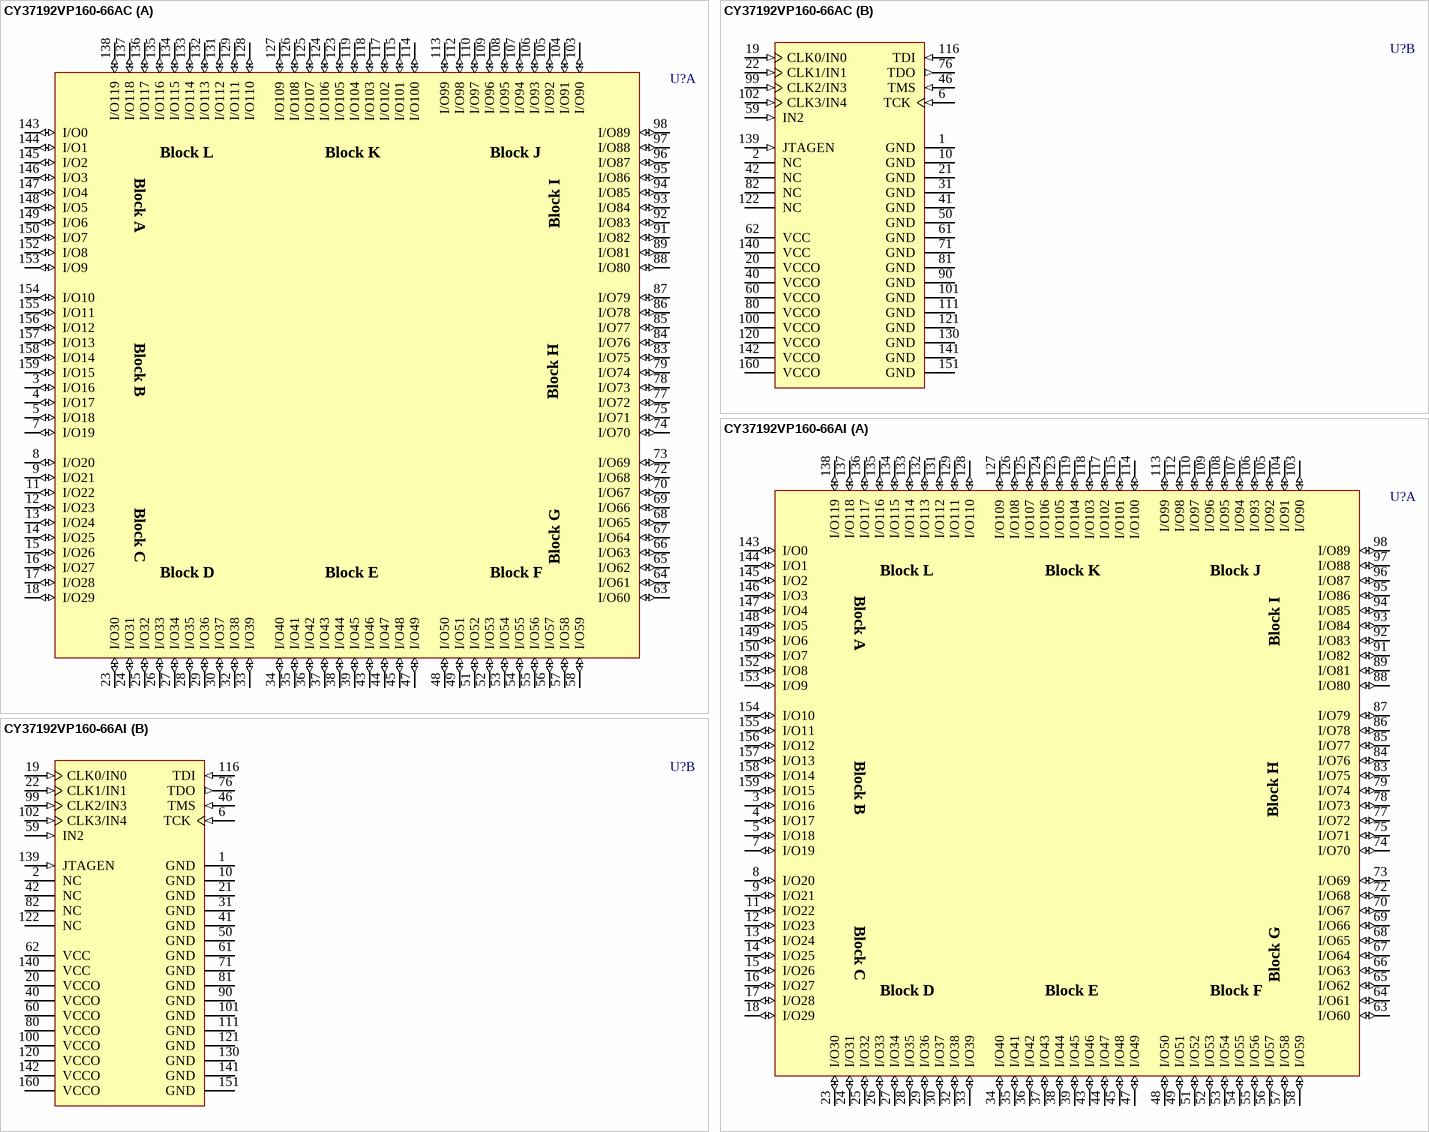
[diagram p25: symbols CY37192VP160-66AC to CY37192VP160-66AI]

## CY37192VP160-66AC
designator U?
Ultra37000 3.3V, ISR High-Performance CPLD
footprint A160_N (Thin QFP, 160-Leads, Body 24x24mm, Pitch 0.5mm, IPC Medium Density)
footprint A160_L (Thin QFP, 160-Leads, Body 24x24mm, Pitch 0.5mm, IPC High Density)
footprint A160_M (Thin QFP, 160-Leads, Body 24x24mm, Pitch 0.5mm, IPC Low Density)
3D model CY37192VP160-A160 (160-Pin Thin Quad Flat Pack 0.5 mm Pitch)
part A pins: 3 I/O16 (io), 4 I/O17 (io), 5 I/O18 (io), 7 I/O19 (io), 8 I/O20 (io), 9 I/O21 (io), 11 I/O22 (io), 12 I/O23 (io), 13 I/O24 (io), 14 I/O25 (io), 15 I/O26 (io), 16 I/O27 (io), 17 I/O28 (io), 18 I/O29 (io), 23 I/O30 (io), 24 I/O31 (io), 25 I/O32 (io), 26 I/O33 (io), 27 I/O34 (io), 28 I/O35 (io), 29 I/O36 (io), 30 I/O37 (io), 32 I/O38 (io), 33 I/O39 (io), 34 I/O40 (io), 35 I/O41 (io), 36 I/O42 (io), 37 I/O43 (io), 38 I/O44 (io), 39 I/O45 (io), 43 I/O46 (io), 44 I/O47 (io), 45 I/O48 (io), 47 I/O49 (io), 48 I/O50 (io), 49 I/O51 (io), 51 I/O52 (io), 52 I/O53 (io), 53 I/O54 (io), 54 I/O55 (io), 55 I/O56 (io), 56 I/O57 (io), 57 I/O58 (io), 58 I/O59 (io), 63 I/O60 (io), 64 I/O61 (io), 65 I/O62 (io), 66 I/O63 (io), 67 I/O64 (io), 68 I/O65 (io), 69 I/O66 (io), 70 I/O67 (io), 72 I/O68 (io), 73 I/O69 (io), 74 I/O70 (io), 75 I/O71 (io), 77 I/O72 (io), 78 I/O73 (io), 79 I/O74 (io), 83 I/O75 (io), 84 I/O76 (io), 85 I/O77 (io), 86 I/O78 (io), 87 I/O79 (io), 88 I/O80 (io), 89 I/O81 (io), 91 I/O82 (io), 92 I/O83 (io), 93 I/O84 (io), 94 I/O85 (io), 95 I/O86 (io), 96 I/O87 (io), 97 I/O88 (io), 98 I/O89 (io), 103 I/O90 (io), 104 I/O91 (io), 105 I/O92 (io), 106 I/O93 (io), 107 I/O94 (io), 108 I/O95 (io), 109 I/O96 (io), 110 I/O97 (io), 112 I/O98 (io), 113 I/O99 (io), 114 I/O100 (io), 115 I/O101 (io), 117 I/O102 (io), 118 I/O103 (io), 119 I/O104 (io), 123 I/O105 (io), 124 I/O106 (io), 125 I/O107 (io), 126 I/O108 (io), 127 I/O109 (io), 128 I/O110 (io), 129 I/O111 (io), 131 I/O112 (io), 132 I/O113 (io), 133 I/O114 (io), 134 I/O115 (io), 135 I/O116 (io), 136 I/O117 (io), 137 I/O118 (io), 138 I/O119 (io), 143 I/O0 (io), 144 I/O1 (io), 145 I/O2 (io), 146 I/O3 (io), 147 I/O4 (io), 148 I/O5 (io), 149 I/O6 (io), 150 I/O7 (io), 152 I/O8 (io), 153 I/O9 (io), 154 I/O10 (io), 155 I/O11 (io), 156 I/O12 (io), 157 I/O13 (io), 158 I/O14 (io), 159 I/O15 (io)
part B pins: 1 GND (power), 2 NC, 6 TCK (in), 10 GND (power), 19 CLK0/IN0 (in), 20 VCCO (power), 21 GND (power), 22 CLK1/IN1 (in), 31 GND (power), 40 VCCO (power), 41 GND (power), 42 NC, 46 TMS (in), 50 GND (power), 59 IN2 (in), 60 VCCO (power), 61 GND (power), 62 VCC (power), 71 GND (power), 76 TDO (out), 80 VCCO (power), 81 GND (power), 82 NC, 90 GND (power), 99 CLK2/IN3 (in), 100 VCCO (power), 101 GND (power), 102 CLK3/IN4 (in), 111 GND (power), 116 TDI (in), 120 VCCO (power), 121 GND (power), 122 NC, 130 GND (power), 139 JTAGEN (in), 140 VCC (power), 141 GND (power), 142 VCCO (power), 151 GND (power), 160 VCCO (power)

## CY37192VP160-66AI
designator U?
Ultra37000 3.3V, ISR High-Performance CPLD
footprint A160_N (Thin QFP, 160-Leads, Body 24x24mm, Pitch 0.5mm, IPC Medium Density)
footprint A160_L (Thin QFP, 160-Leads, Body 24x24mm, Pitch 0.5mm, IPC High Density)
footprint A160_M (Thin QFP, 160-Leads, Body 24x24mm, Pitch 0.5mm, IPC Low Density)
3D model CY37192VP160-A160 (160-Pin Thin Quad Flat Pack 0.5 mm Pitch)
part A pins: 3 I/O16 (io), 4 I/O17 (io), 5 I/O18 (io), 7 I/O19 (io), 8 I/O20 (io), 9 I/O21 (io), 11 I/O22 (io), 12 I/O23 (io), 13 I/O24 (io), 14 I/O25 (io), 15 I/O26 (io), 16 I/O27 (io), 17 I/O28 (io), 18 I/O29 (io), 23 I/O30 (io), 24 I/O31 (io), 25 I/O32 (io), 26 I/O33 (io), 27 I/O34 (io), 28 I/O35 (io), 29 I/O36 (io), 30 I/O37 (io), 32 I/O38 (io), 33 I/O39 (io), 34 I/O40 (io), 35 I/O41 (io), 36 I/O42 (io), 37 I/O43 (io), 38 I/O44 (io), 39 I/O45 (io), 43 I/O46 (io), 44 I/O47 (io), 45 I/O48 (io), 47 I/O49 (io), 48 I/O50 (io), 49 I/O51 (io), 51 I/O52 (io), 52 I/O53 (io), 53 I/O54 (io), 54 I/O55 (io), 55 I/O56 (io), 56 I/O57 (io), 57 I/O58 (io), 58 I/O59 (io), 63 I/O60 (io), 64 I/O61 (io), 65 I/O62 (io), 66 I/O63 (io), 67 I/O64 (io), 68 I/O65 (io), 69 I/O66 (io), 70 I/O67 (io), 72 I/O68 (io), 73 I/O69 (io), 74 I/O70 (io), 75 I/O71 (io), 77 I/O72 (io), 78 I/O73 (io), 79 I/O74 (io), 83 I/O75 (io), 84 I/O76 (io), 85 I/O77 (io), 86 I/O78 (io), 87 I/O79 (io), 88 I/O80 (io), 89 I/O81 (io), 91 I/O82 (io), 92 I/O83 (io), 93 I/O84 (io), 94 I/O85 (io), 95 I/O86 (io), 96 I/O87 (io), 97 I/O88 (io), 98 I/O89 (io), 103 I/O90 (io), 104 I/O91 (io), 105 I/O92 (io), 106 I/O93 (io), 107 I/O94 (io), 108 I/O95 (io), 109 I/O96 (io), 110 I/O97 (io), 112 I/O98 (io), 113 I/O99 (io), 114 I/O100 (io), 115 I/O101 (io), 117 I/O102 (io), 118 I/O103 (io), 119 I/O104 (io), 123 I/O105 (io), 124 I/O106 (io), 125 I/O107 (io), 126 I/O108 (io), 127 I/O109 (io), 128 I/O110 (io), 129 I/O111 (io), 131 I/O112 (io), 132 I/O113 (io), 133 I/O114 (io), 134 I/O115 (io), 135 I/O116 (io), 136 I/O117 (io), 137 I/O118 (io), 138 I/O119 (io), 143 I/O0 (io), 144 I/O1 (io), 145 I/O2 (io), 146 I/O3 (io), 147 I/O4 (io), 148 I/O5 (io), 149 I/O6 (io), 150 I/O7 (io), 152 I/O8 (io), 153 I/O9 (io), 154 I/O10 (io), 155 I/O11 (io), 156 I/O12 (io), 157 I/O13 (io), 158 I/O14 (io), 159 I/O15 (io)
part B pins: 1 GND (power), 2 NC, 6 TCK (in), 10 GND (power), 19 CLK0/IN0 (in), 20 VCCO (power), 21 GND (power), 22 CLK1/IN1 (in), 31 GND (power), 40 VCCO (power), 41 GND (power), 42 NC, 46 TMS (in), 50 GND (power), 59 IN2 (in), 60 VCCO (power), 61 GND (power), 62 VCC (power), 71 GND (power), 76 TDO (out), 80 VCCO (power), 81 GND (power), 82 NC, 90 GND (power), 99 CLK2/IN3 (in), 100 VCCO (power), 101 GND (power), 102 CLK3/IN4 (in), 111 GND (power), 116 TDI (in), 120 VCCO (power), 121 GND (power), 122 NC, 130 GND (power), 139 JTAGEN (in), 140 VCC (power), 141 GND (power), 142 VCCO (power), 151 GND (power), 160 VCCO (power)

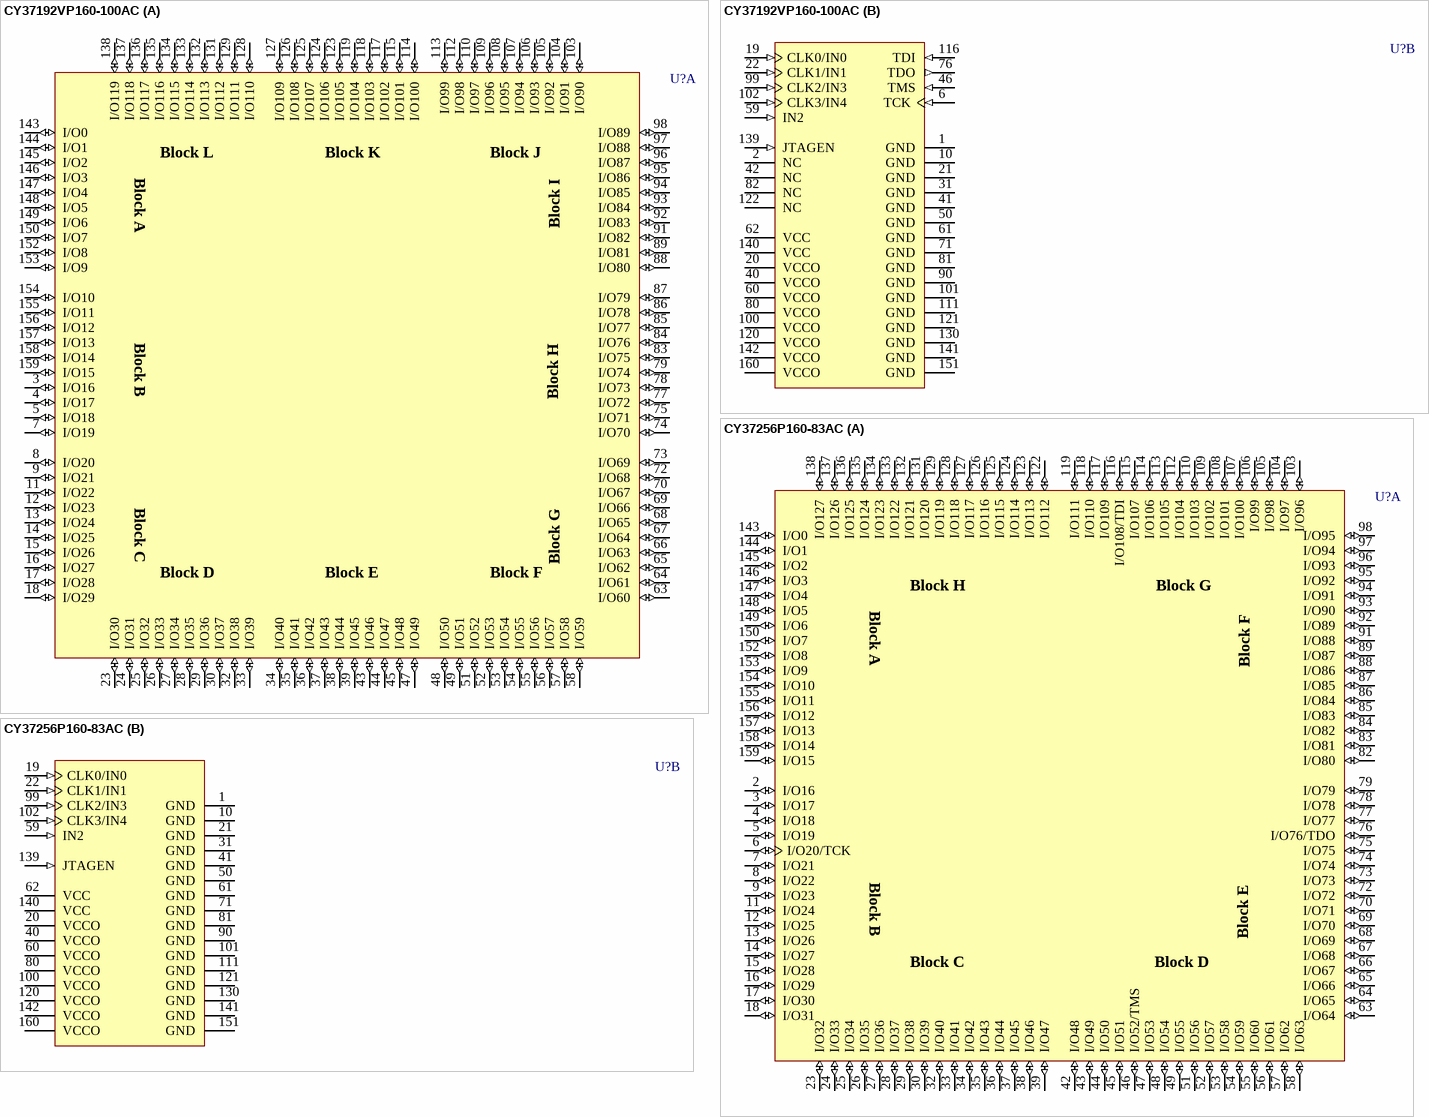
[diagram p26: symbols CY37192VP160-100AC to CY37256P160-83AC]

## CY37192VP160-100AC
designator U?
Ultra37000 3.3V, ISR High-Performance CPLD
footprint A160_N (Thin QFP, 160-Leads, Body 24x24mm, Pitch 0.5mm, IPC Medium Density)
footprint A160_L (Thin QFP, 160-Leads, Body 24x24mm, Pitch 0.5mm, IPC High Density)
footprint A160_M (Thin QFP, 160-Leads, Body 24x24mm, Pitch 0.5mm, IPC Low Density)
3D model CY37192VP160-A160 (160-Pin Thin Quad Flat Pack 0.5 mm Pitch)
part A pins: 3 I/O16 (io), 4 I/O17 (io), 5 I/O18 (io), 7 I/O19 (io), 8 I/O20 (io), 9 I/O21 (io), 11 I/O22 (io), 12 I/O23 (io), 13 I/O24 (io), 14 I/O25 (io), 15 I/O26 (io), 16 I/O27 (io), 17 I/O28 (io), 18 I/O29 (io), 23 I/O30 (io), 24 I/O31 (io), 25 I/O32 (io), 26 I/O33 (io), 27 I/O34 (io), 28 I/O35 (io), 29 I/O36 (io), 30 I/O37 (io), 32 I/O38 (io), 33 I/O39 (io), 34 I/O40 (io), 35 I/O41 (io), 36 I/O42 (io), 37 I/O43 (io), 38 I/O44 (io), 39 I/O45 (io), 43 I/O46 (io), 44 I/O47 (io), 45 I/O48 (io), 47 I/O49 (io), 48 I/O50 (io), 49 I/O51 (io), 51 I/O52 (io), 52 I/O53 (io), 53 I/O54 (io), 54 I/O55 (io), 55 I/O56 (io), 56 I/O57 (io), 57 I/O58 (io), 58 I/O59 (io), 63 I/O60 (io), 64 I/O61 (io), 65 I/O62 (io), 66 I/O63 (io), 67 I/O64 (io), 68 I/O65 (io), 69 I/O66 (io), 70 I/O67 (io), 72 I/O68 (io), 73 I/O69 (io), 74 I/O70 (io), 75 I/O71 (io), 77 I/O72 (io), 78 I/O73 (io), 79 I/O74 (io), 83 I/O75 (io), 84 I/O76 (io), 85 I/O77 (io), 86 I/O78 (io), 87 I/O79 (io), 88 I/O80 (io), 89 I/O81 (io), 91 I/O82 (io), 92 I/O83 (io), 93 I/O84 (io), 94 I/O85 (io), 95 I/O86 (io), 96 I/O87 (io), 97 I/O88 (io), 98 I/O89 (io), 103 I/O90 (io), 104 I/O91 (io), 105 I/O92 (io), 106 I/O93 (io), 107 I/O94 (io), 108 I/O95 (io), 109 I/O96 (io), 110 I/O97 (io), 112 I/O98 (io), 113 I/O99 (io), 114 I/O100 (io), 115 I/O101 (io), 117 I/O102 (io), 118 I/O103 (io), 119 I/O104 (io), 123 I/O105 (io), 124 I/O106 (io), 125 I/O107 (io), 126 I/O108 (io), 127 I/O109 (io), 128 I/O110 (io), 129 I/O111 (io), 131 I/O112 (io), 132 I/O113 (io), 133 I/O114 (io), 134 I/O115 (io), 135 I/O116 (io), 136 I/O117 (io), 137 I/O118 (io), 138 I/O119 (io), 143 I/O0 (io), 144 I/O1 (io), 145 I/O2 (io), 146 I/O3 (io), 147 I/O4 (io), 148 I/O5 (io), 149 I/O6 (io), 150 I/O7 (io), 152 I/O8 (io), 153 I/O9 (io), 154 I/O10 (io), 155 I/O11 (io), 156 I/O12 (io), 157 I/O13 (io), 158 I/O14 (io), 159 I/O15 (io)
part B pins: 1 GND (power), 2 NC, 6 TCK (in), 10 GND (power), 19 CLK0/IN0 (in), 20 VCCO (power), 21 GND (power), 22 CLK1/IN1 (in), 31 GND (power), 40 VCCO (power), 41 GND (power), 42 NC, 46 TMS (in), 50 GND (power), 59 IN2 (in), 60 VCCO (power), 61 GND (power), 62 VCC (power), 71 GND (power), 76 TDO (out), 80 VCCO (power), 81 GND (power), 82 NC, 90 GND (power), 99 CLK2/IN3 (in), 100 VCCO (power), 101 GND (power), 102 CLK3/IN4 (in), 111 GND (power), 116 TDI (in), 120 VCCO (power), 121 GND (power), 122 NC, 130 GND (power), 139 JTAGEN (in), 140 VCC (power), 141 GND (power), 142 VCCO (power), 151 GND (power), 160 VCCO (power)

## CY37256P160-83AC
designator U?
Ultra37000 5V, ISR High-Performance CPLD
footprint A160_N (Thin QFP, 160-Leads, Body 24x24mm, Pitch 0.5mm, IPC Medium Density)
footprint A160_L (Thin QFP, 160-Leads, Body 24x24mm, Pitch 0.5mm, IPC High Density)
footprint A160_M (Thin QFP, 160-Leads, Body 24x24mm, Pitch 0.5mm, IPC Low Density)
3D model CY37256P160-A160 (160-Pin Thin Quad Flat Pack 0.5 mm Pitch)
part A pins: 2 I/O16 (io), 3 I/O17 (io), 4 I/O18 (io), 5 I/O19 (io), 6 I/O20/TCK (io), 7 I/O21 (io), 8 I/O22 (io), 9 I/O23 (io), 11 I/O24 (io), 12 I/O25 (io), 13 I/O26 (io), 14 I/O27 (io), 15 I/O28 (io), 16 I/O29 (io), 17 I/O30 (io), 18 I/O31 (io), 23 I/O32 (io), 24 I/O33 (io), 25 I/O34 (io), 26 I/O35 (io), 27 I/O36 (io), 28 I/O37 (io), 29 I/O38 (io), 30 I/O39 (io), 32 I/O40 (io), 33 I/O41 (io), 34 I/O42 (io), 35 I/O43 (io), 36 I/O44 (io), 37 I/O45 (io), 38 I/O46 (io), 39 I/O47 (io), 42 I/O48 (io), 43 I/O49 (io), 44 I/O50 (io), 45 I/O51 (io), 46 I/O52/TMS (io), 47 I/O53 (io), 48 I/O54 (io), 49 I/O55 (io), 51 I/O56 (io), 52 I/O57 (io), 53 I/O58 (io), 54 I/O59 (io), 55 I/O60 (io), 56 I/O61 (io), 57 I/O62 (io), 58 I/O63 (io), 63 I/O64 (io), 64 I/O65 (io), 65 I/O66 (io), 66 I/O67 (io), 67 I/O68 (io), 68 I/O69 (io), 69 I/O70 (io), 70 I/O71 (io), 72 I/O72 (io), 73 I/O73 (io), 74 I/O74 (io), 75 I/O75 (io), 76 I/O76/TDO (io), 77 I/O77 (io), 78 I/O78 (io), 79 I/O79 (io), 82 I/O80 (io), 83 I/O81 (io), 84 I/O82 (io), 85 I/O83 (io), 86 I/O84 (io), 87 I/O85 (io), 88 I/O86 (io), 89 I/O87 (io), 91 I/O88 (io), 92 I/O89 (io), 93 I/O90 (io), 94 I/O91 (io), 95 I/O92 (io), 96 I/O93 (io), 97 I/O94 (io), 98 I/O95 (io), 103 I/O96 (io), 104 I/O97 (io), 105 I/O98 (io), 106 I/O99 (io), 107 I/O100 (io), 108 I/O101 (io), 109 I/O102 (io), 110 I/O103 (io), 112 I/O104 (io), 113 I/O105 (io), 114 I/O106 (io), 115 I/O107 (io), 116 I/O108/TDI (io), 117 I/O109 (io), 118 I/O110 (io), 119 I/O111 (io), 122 I/O112 (io), 123 I/O113 (io), 124 I/O114 (io), 125 I/O115 (io), 126 I/O116 (io), 127 I/O117 (io), 128 I/O118 (io), 129 I/O119 (io), 131 I/O120 (io), 132 I/O121 (io), 133 I/O122 (io), 134 I/O123 (io), 135 I/O124 (io), 136 I/O125 (io), 137 I/O126 (io), 138 I/O127 (io), 143 I/O0 (io), 144 I/O1 (io), 145 I/O2 (io), 146 I/O3 (io), 147 I/O4 (io), 148 I/O5 (io), 149 I/O6 (io), 150 I/O7 (io), 152 I/O8 (io), 153 I/O9 (io), 154 I/O10 (io), 155 I/O11 (io), 156 I/O12 (io), 157 I/O13 (io), 158 I/O14 (io), 159 I/O15 (io)
part B pins: 1 GND (power), 10 GND (power), 19 CLK0/IN0 (in), 20 VCCO (power), 21 GND (power), 22 CLK1/IN1 (in), 31 GND (power), 40 VCCO (power), 41 GND (power), 50 GND (power), 59 IN2 (in), 60 VCCO (power), 61 GND (power), 62 VCC (power), 71 GND (power), 80 VCCO (power), 81 GND (power), 90 GND (power), 99 CLK2/IN3 (in), 100 VCCO (power), 101 GND (power), 102 CLK3/IN4 (in), 111 GND (power), 120 VCCO (power), 121 GND (power), 130 GND (power), 139 JTAGEN (in), 140 VCC (power), 141 GND (power), 142 VCCO (power), 151 GND (power), 160 VCCO (power)

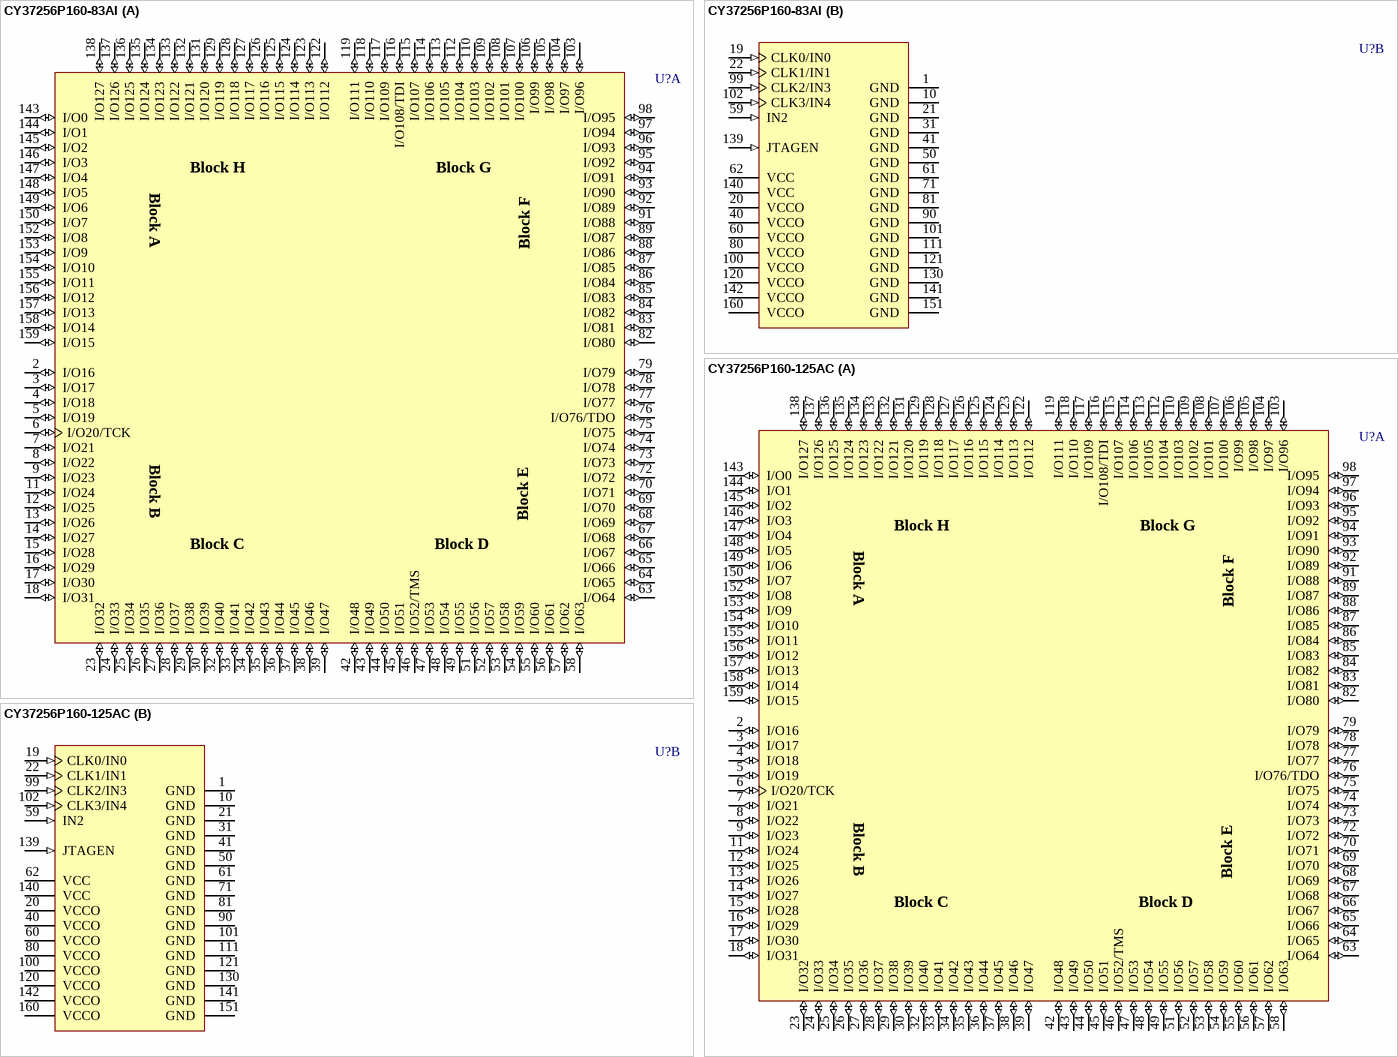
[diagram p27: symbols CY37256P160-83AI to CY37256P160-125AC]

## CY37256P160-83AI
designator U?
Ultra37000 5V, ISR High-Performance CPLD
footprint A160_N (Thin QFP, 160-Leads, Body 24x24mm, Pitch 0.5mm, IPC Medium Density)
footprint A160_L (Thin QFP, 160-Leads, Body 24x24mm, Pitch 0.5mm, IPC High Density)
footprint A160_M (Thin QFP, 160-Leads, Body 24x24mm, Pitch 0.5mm, IPC Low Density)
3D model CY37256P160-A160 (160-Pin Thin Quad Flat Pack 0.5 mm Pitch)
part A pins: 2 I/O16 (io), 3 I/O17 (io), 4 I/O18 (io), 5 I/O19 (io), 6 I/O20/TCK (io), 7 I/O21 (io), 8 I/O22 (io), 9 I/O23 (io), 11 I/O24 (io), 12 I/O25 (io), 13 I/O26 (io), 14 I/O27 (io), 15 I/O28 (io), 16 I/O29 (io), 17 I/O30 (io), 18 I/O31 (io), 23 I/O32 (io), 24 I/O33 (io), 25 I/O34 (io), 26 I/O35 (io), 27 I/O36 (io), 28 I/O37 (io), 29 I/O38 (io), 30 I/O39 (io), 32 I/O40 (io), 33 I/O41 (io), 34 I/O42 (io), 35 I/O43 (io), 36 I/O44 (io), 37 I/O45 (io), 38 I/O46 (io), 39 I/O47 (io), 42 I/O48 (io), 43 I/O49 (io), 44 I/O50 (io), 45 I/O51 (io), 46 I/O52/TMS (io), 47 I/O53 (io), 48 I/O54 (io), 49 I/O55 (io), 51 I/O56 (io), 52 I/O57 (io), 53 I/O58 (io), 54 I/O59 (io), 55 I/O60 (io), 56 I/O61 (io), 57 I/O62 (io), 58 I/O63 (io), 63 I/O64 (io), 64 I/O65 (io), 65 I/O66 (io), 66 I/O67 (io), 67 I/O68 (io), 68 I/O69 (io), 69 I/O70 (io), 70 I/O71 (io), 72 I/O72 (io), 73 I/O73 (io), 74 I/O74 (io), 75 I/O75 (io), 76 I/O76/TDO (io), 77 I/O77 (io), 78 I/O78 (io), 79 I/O79 (io), 82 I/O80 (io), 83 I/O81 (io), 84 I/O82 (io), 85 I/O83 (io), 86 I/O84 (io), 87 I/O85 (io), 88 I/O86 (io), 89 I/O87 (io), 91 I/O88 (io), 92 I/O89 (io), 93 I/O90 (io), 94 I/O91 (io), 95 I/O92 (io), 96 I/O93 (io), 97 I/O94 (io), 98 I/O95 (io), 103 I/O96 (io), 104 I/O97 (io), 105 I/O98 (io), 106 I/O99 (io), 107 I/O100 (io), 108 I/O101 (io), 109 I/O102 (io), 110 I/O103 (io), 112 I/O104 (io), 113 I/O105 (io), 114 I/O106 (io), 115 I/O107 (io), 116 I/O108/TDI (io), 117 I/O109 (io), 118 I/O110 (io), 119 I/O111 (io), 122 I/O112 (io), 123 I/O113 (io), 124 I/O114 (io), 125 I/O115 (io), 126 I/O116 (io), 127 I/O117 (io), 128 I/O118 (io), 129 I/O119 (io), 131 I/O120 (io), 132 I/O121 (io), 133 I/O122 (io), 134 I/O123 (io), 135 I/O124 (io), 136 I/O125 (io), 137 I/O126 (io), 138 I/O127 (io), 143 I/O0 (io), 144 I/O1 (io), 145 I/O2 (io), 146 I/O3 (io), 147 I/O4 (io), 148 I/O5 (io), 149 I/O6 (io), 150 I/O7 (io), 152 I/O8 (io), 153 I/O9 (io), 154 I/O10 (io), 155 I/O11 (io), 156 I/O12 (io), 157 I/O13 (io), 158 I/O14 (io), 159 I/O15 (io)
part B pins: 1 GND (power), 10 GND (power), 19 CLK0/IN0 (in), 20 VCCO (power), 21 GND (power), 22 CLK1/IN1 (in), 31 GND (power), 40 VCCO (power), 41 GND (power), 50 GND (power), 59 IN2 (in), 60 VCCO (power), 61 GND (power), 62 VCC (power), 71 GND (power), 80 VCCO (power), 81 GND (power), 90 GND (power), 99 CLK2/IN3 (in), 100 VCCO (power), 101 GND (power), 102 CLK3/IN4 (in), 111 GND (power), 120 VCCO (power), 121 GND (power), 130 GND (power), 139 JTAGEN (in), 140 VCC (power), 141 GND (power), 142 VCCO (power), 151 GND (power), 160 VCCO (power)

## CY37256P160-125AC
designator U?
Ultra37000 5V, ISR High-Performance CPLD
footprint A160_N (Thin QFP, 160-Leads, Body 24x24mm, Pitch 0.5mm, IPC Medium Density)
footprint A160_L (Thin QFP, 160-Leads, Body 24x24mm, Pitch 0.5mm, IPC High Density)
footprint A160_M (Thin QFP, 160-Leads, Body 24x24mm, Pitch 0.5mm, IPC Low Density)
3D model CY37256P160-A160 (160-Pin Thin Quad Flat Pack 0.5 mm Pitch)
part A pins: 2 I/O16 (io), 3 I/O17 (io), 4 I/O18 (io), 5 I/O19 (io), 6 I/O20/TCK (io), 7 I/O21 (io), 8 I/O22 (io), 9 I/O23 (io), 11 I/O24 (io), 12 I/O25 (io), 13 I/O26 (io), 14 I/O27 (io), 15 I/O28 (io), 16 I/O29 (io), 17 I/O30 (io), 18 I/O31 (io), 23 I/O32 (io), 24 I/O33 (io), 25 I/O34 (io), 26 I/O35 (io), 27 I/O36 (io), 28 I/O37 (io), 29 I/O38 (io), 30 I/O39 (io), 32 I/O40 (io), 33 I/O41 (io), 34 I/O42 (io), 35 I/O43 (io), 36 I/O44 (io), 37 I/O45 (io), 38 I/O46 (io), 39 I/O47 (io), 42 I/O48 (io), 43 I/O49 (io), 44 I/O50 (io), 45 I/O51 (io), 46 I/O52/TMS (io), 47 I/O53 (io), 48 I/O54 (io), 49 I/O55 (io), 51 I/O56 (io), 52 I/O57 (io), 53 I/O58 (io), 54 I/O59 (io), 55 I/O60 (io), 56 I/O61 (io), 57 I/O62 (io), 58 I/O63 (io), 63 I/O64 (io), 64 I/O65 (io), 65 I/O66 (io), 66 I/O67 (io), 67 I/O68 (io), 68 I/O69 (io), 69 I/O70 (io), 70 I/O71 (io), 72 I/O72 (io), 73 I/O73 (io), 74 I/O74 (io), 75 I/O75 (io), 76 I/O76/TDO (io), 77 I/O77 (io), 78 I/O78 (io), 79 I/O79 (io), 82 I/O80 (io), 83 I/O81 (io), 84 I/O82 (io), 85 I/O83 (io), 86 I/O84 (io), 87 I/O85 (io), 88 I/O86 (io), 89 I/O87 (io), 91 I/O88 (io), 92 I/O89 (io), 93 I/O90 (io), 94 I/O91 (io), 95 I/O92 (io), 96 I/O93 (io), 97 I/O94 (io), 98 I/O95 (io), 103 I/O96 (io), 104 I/O97 (io), 105 I/O98 (io), 106 I/O99 (io), 107 I/O100 (io), 108 I/O101 (io), 109 I/O102 (io), 110 I/O103 (io), 112 I/O104 (io), 113 I/O105 (io), 114 I/O106 (io), 115 I/O107 (io), 116 I/O108/TDI (io), 117 I/O109 (io), 118 I/O110 (io), 119 I/O111 (io), 122 I/O112 (io), 123 I/O113 (io), 124 I/O114 (io), 125 I/O115 (io), 126 I/O116 (io), 127 I/O117 (io), 128 I/O118 (io), 129 I/O119 (io), 131 I/O120 (io), 132 I/O121 (io), 133 I/O122 (io), 134 I/O123 (io), 135 I/O124 (io), 136 I/O125 (io), 137 I/O126 (io), 138 I/O127 (io), 143 I/O0 (io), 144 I/O1 (io), 145 I/O2 (io), 146 I/O3 (io), 147 I/O4 (io), 148 I/O5 (io), 149 I/O6 (io), 150 I/O7 (io), 152 I/O8 (io), 153 I/O9 (io), 154 I/O10 (io), 155 I/O11 (io), 156 I/O12 (io), 157 I/O13 (io), 158 I/O14 (io), 159 I/O15 (io)
part B pins: 1 GND (power), 10 GND (power), 19 CLK0/IN0 (in), 20 VCCO (power), 21 GND (power), 22 CLK1/IN1 (in), 31 GND (power), 40 VCCO (power), 41 GND (power), 50 GND (power), 59 IN2 (in), 60 VCCO (power), 61 GND (power), 62 VCC (power), 71 GND (power), 80 VCCO (power), 81 GND (power), 90 GND (power), 99 CLK2/IN3 (in), 100 VCCO (power), 101 GND (power), 102 CLK3/IN4 (in), 111 GND (power), 120 VCCO (power), 121 GND (power), 130 GND (power), 139 JTAGEN (in), 140 VCC (power), 141 GND (power), 142 VCCO (power), 151 GND (power), 160 VCCO (power)

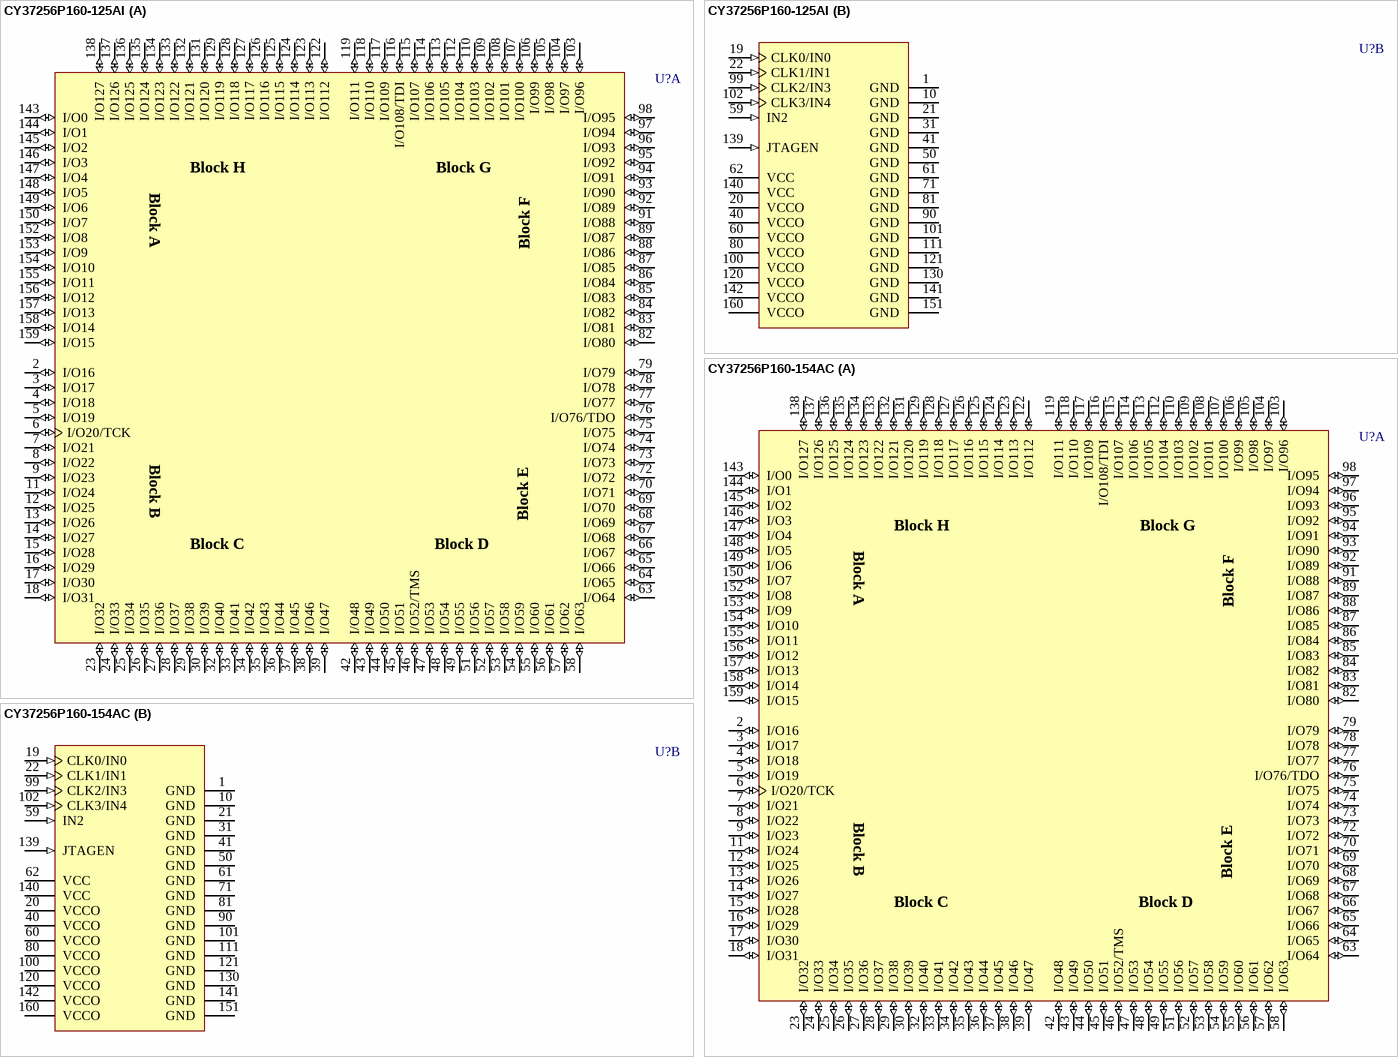
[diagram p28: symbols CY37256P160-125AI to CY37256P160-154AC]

## CY37256P160-125AI
designator U?
Ultra37000 5V, ISR High-Performance CPLD
footprint A160_N (Thin QFP, 160-Leads, Body 24x24mm, Pitch 0.5mm, IPC Medium Density)
footprint A160_L (Thin QFP, 160-Leads, Body 24x24mm, Pitch 0.5mm, IPC High Density)
footprint A160_M (Thin QFP, 160-Leads, Body 24x24mm, Pitch 0.5mm, IPC Low Density)
3D model CY37256P160-A160 (160-Pin Thin Quad Flat Pack 0.5 mm Pitch)
part A pins: 2 I/O16 (io), 3 I/O17 (io), 4 I/O18 (io), 5 I/O19 (io), 6 I/O20/TCK (io), 7 I/O21 (io), 8 I/O22 (io), 9 I/O23 (io), 11 I/O24 (io), 12 I/O25 (io), 13 I/O26 (io), 14 I/O27 (io), 15 I/O28 (io), 16 I/O29 (io), 17 I/O30 (io), 18 I/O31 (io), 23 I/O32 (io), 24 I/O33 (io), 25 I/O34 (io), 26 I/O35 (io), 27 I/O36 (io), 28 I/O37 (io), 29 I/O38 (io), 30 I/O39 (io), 32 I/O40 (io), 33 I/O41 (io), 34 I/O42 (io), 35 I/O43 (io), 36 I/O44 (io), 37 I/O45 (io), 38 I/O46 (io), 39 I/O47 (io), 42 I/O48 (io), 43 I/O49 (io), 44 I/O50 (io), 45 I/O51 (io), 46 I/O52/TMS (io), 47 I/O53 (io), 48 I/O54 (io), 49 I/O55 (io), 51 I/O56 (io), 52 I/O57 (io), 53 I/O58 (io), 54 I/O59 (io), 55 I/O60 (io), 56 I/O61 (io), 57 I/O62 (io), 58 I/O63 (io), 63 I/O64 (io), 64 I/O65 (io), 65 I/O66 (io), 66 I/O67 (io), 67 I/O68 (io), 68 I/O69 (io), 69 I/O70 (io), 70 I/O71 (io), 72 I/O72 (io), 73 I/O73 (io), 74 I/O74 (io), 75 I/O75 (io), 76 I/O76/TDO (io), 77 I/O77 (io), 78 I/O78 (io), 79 I/O79 (io), 82 I/O80 (io), 83 I/O81 (io), 84 I/O82 (io), 85 I/O83 (io), 86 I/O84 (io), 87 I/O85 (io), 88 I/O86 (io), 89 I/O87 (io), 91 I/O88 (io), 92 I/O89 (io), 93 I/O90 (io), 94 I/O91 (io), 95 I/O92 (io), 96 I/O93 (io), 97 I/O94 (io), 98 I/O95 (io), 103 I/O96 (io), 104 I/O97 (io), 105 I/O98 (io), 106 I/O99 (io), 107 I/O100 (io), 108 I/O101 (io), 109 I/O102 (io), 110 I/O103 (io), 112 I/O104 (io), 113 I/O105 (io), 114 I/O106 (io), 115 I/O107 (io), 116 I/O108/TDI (io), 117 I/O109 (io), 118 I/O110 (io), 119 I/O111 (io), 122 I/O112 (io), 123 I/O113 (io), 124 I/O114 (io), 125 I/O115 (io), 126 I/O116 (io), 127 I/O117 (io), 128 I/O118 (io), 129 I/O119 (io), 131 I/O120 (io), 132 I/O121 (io), 133 I/O122 (io), 134 I/O123 (io), 135 I/O124 (io), 136 I/O125 (io), 137 I/O126 (io), 138 I/O127 (io), 143 I/O0 (io), 144 I/O1 (io), 145 I/O2 (io), 146 I/O3 (io), 147 I/O4 (io), 148 I/O5 (io), 149 I/O6 (io), 150 I/O7 (io), 152 I/O8 (io), 153 I/O9 (io), 154 I/O10 (io), 155 I/O11 (io), 156 I/O12 (io), 157 I/O13 (io), 158 I/O14 (io), 159 I/O15 (io)
part B pins: 1 GND (power), 10 GND (power), 19 CLK0/IN0 (in), 20 VCCO (power), 21 GND (power), 22 CLK1/IN1 (in), 31 GND (power), 40 VCCO (power), 41 GND (power), 50 GND (power), 59 IN2 (in), 60 VCCO (power), 61 GND (power), 62 VCC (power), 71 GND (power), 80 VCCO (power), 81 GND (power), 90 GND (power), 99 CLK2/IN3 (in), 100 VCCO (power), 101 GND (power), 102 CLK3/IN4 (in), 111 GND (power), 120 VCCO (power), 121 GND (power), 130 GND (power), 139 JTAGEN (in), 140 VCC (power), 141 GND (power), 142 VCCO (power), 151 GND (power), 160 VCCO (power)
